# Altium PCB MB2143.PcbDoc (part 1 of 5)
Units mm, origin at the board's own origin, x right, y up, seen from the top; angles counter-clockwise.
Board outline 70 x 70 mm, 4 copper layers (Top Layer, Signal Layer 1, Signal Layer 2, Bottom Layer), stack 1.56 mm thick; 272 components, 188 nets, 1083 pads, 1158 vias.
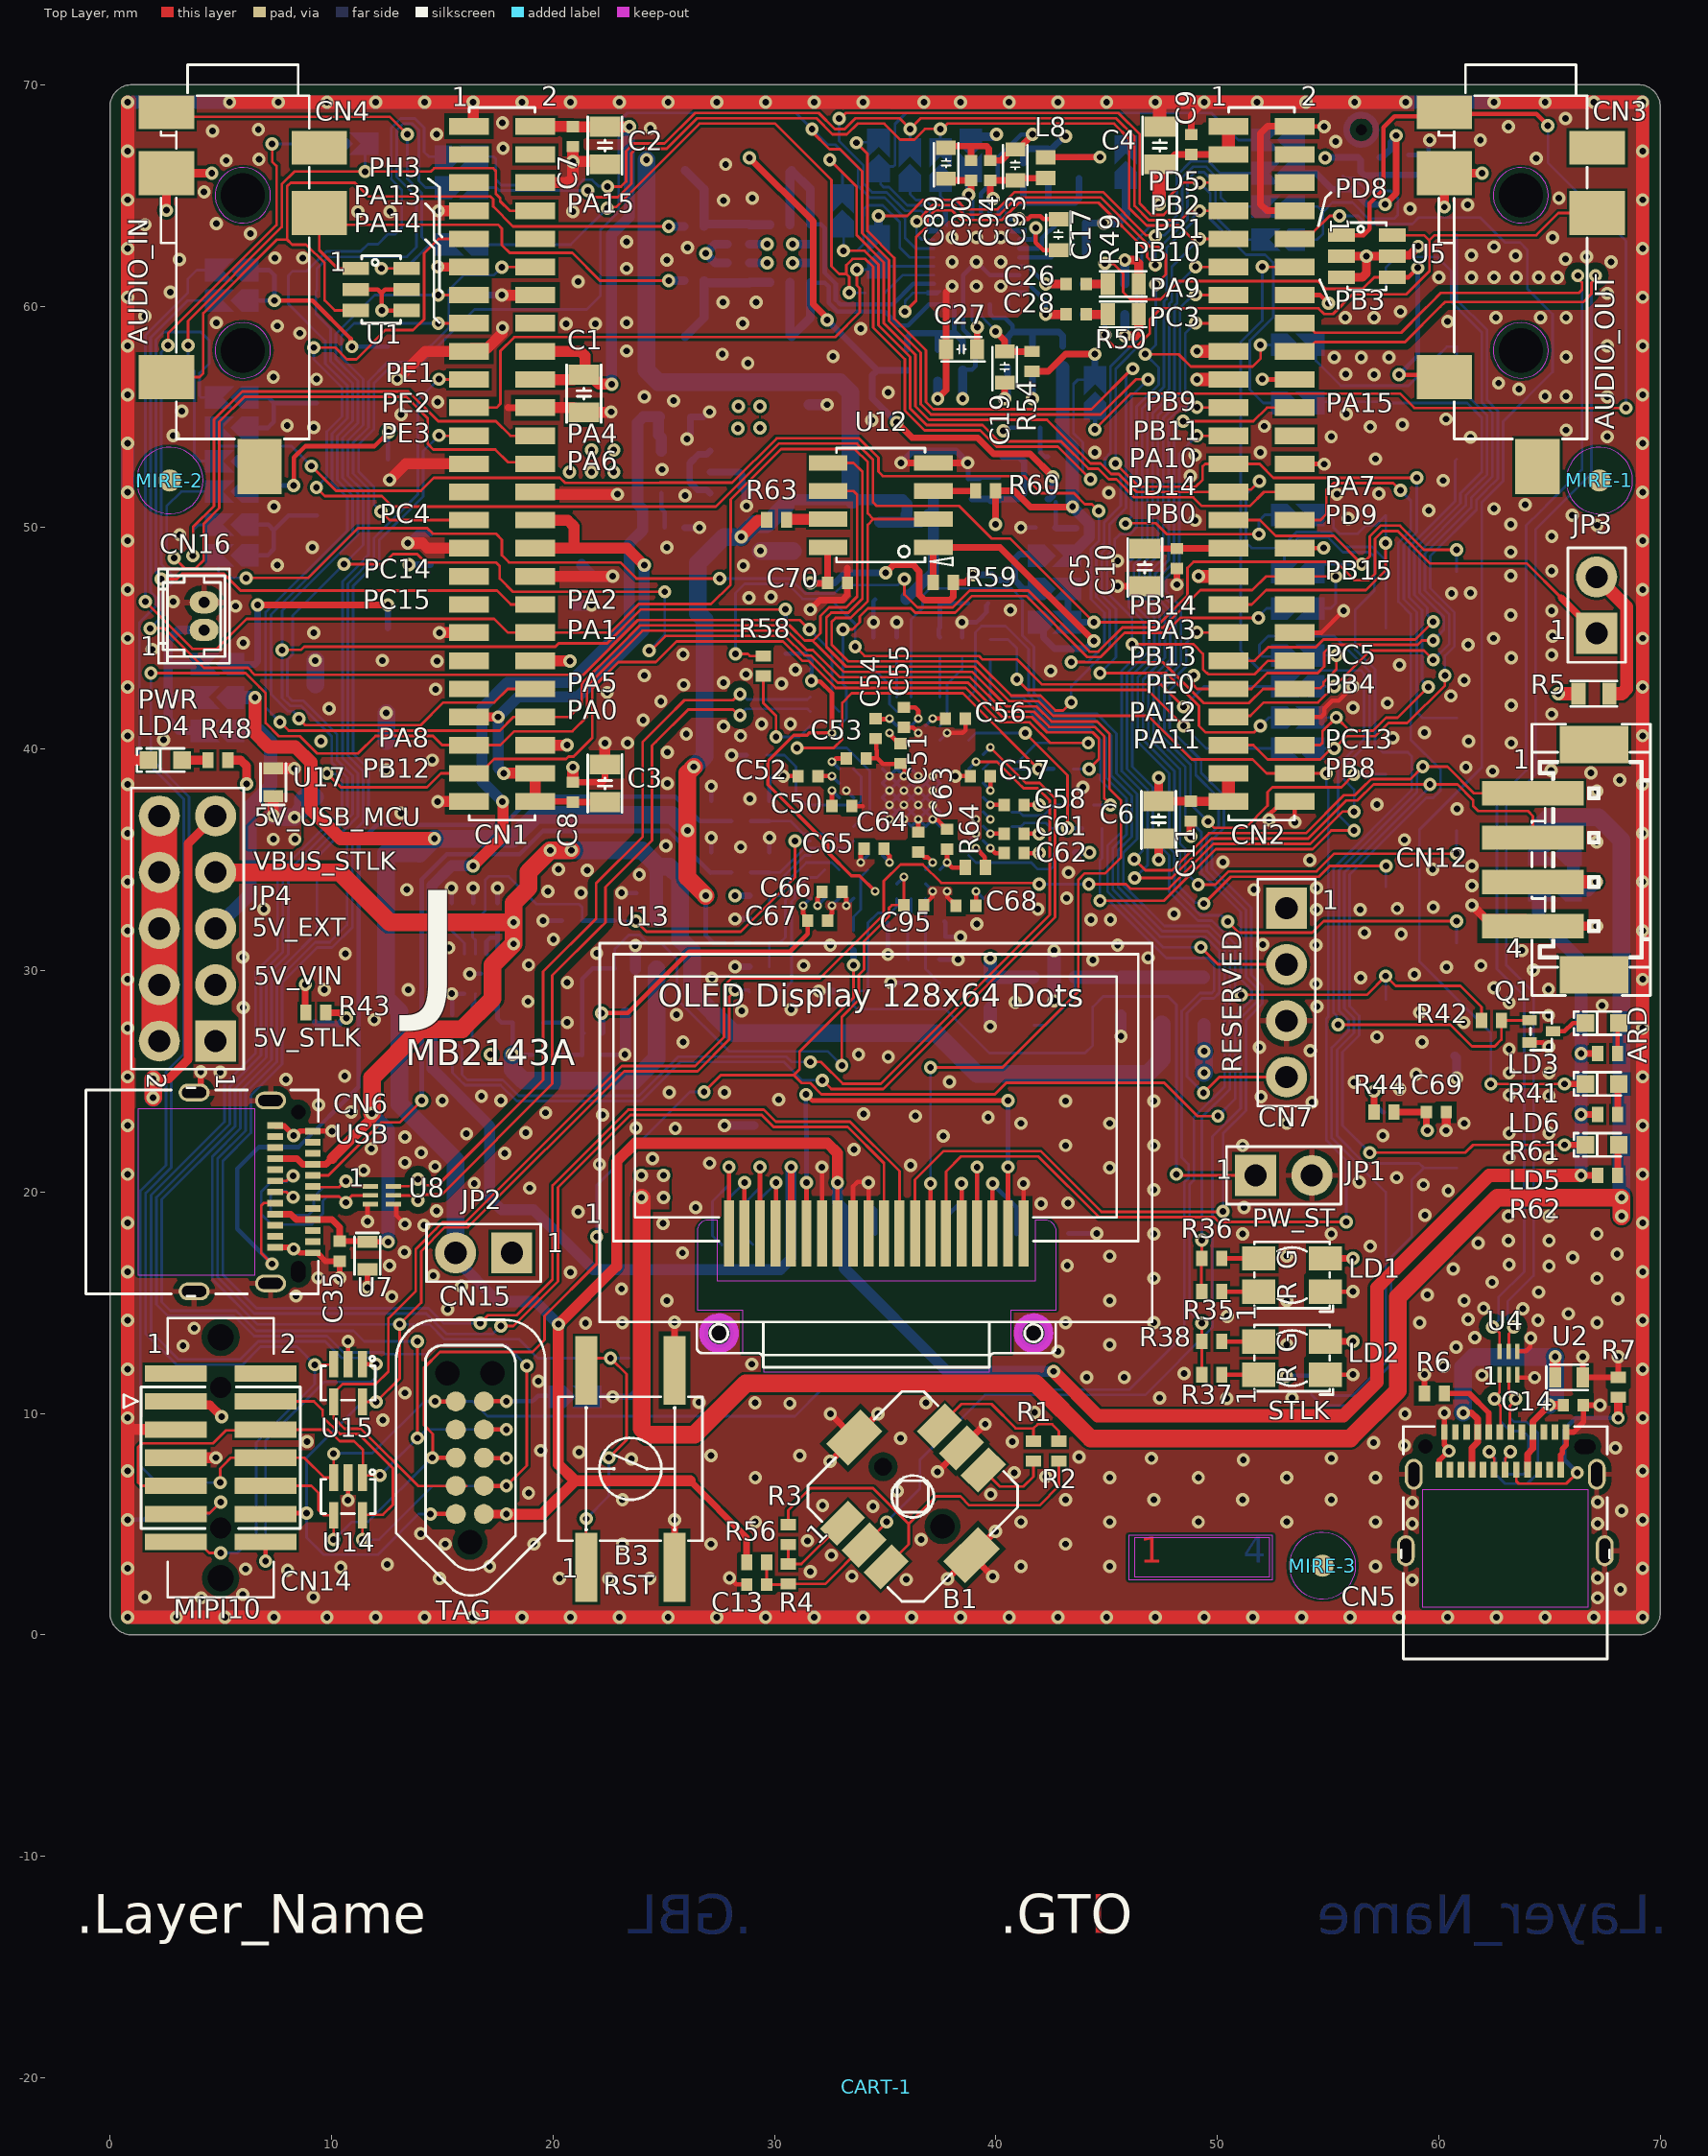
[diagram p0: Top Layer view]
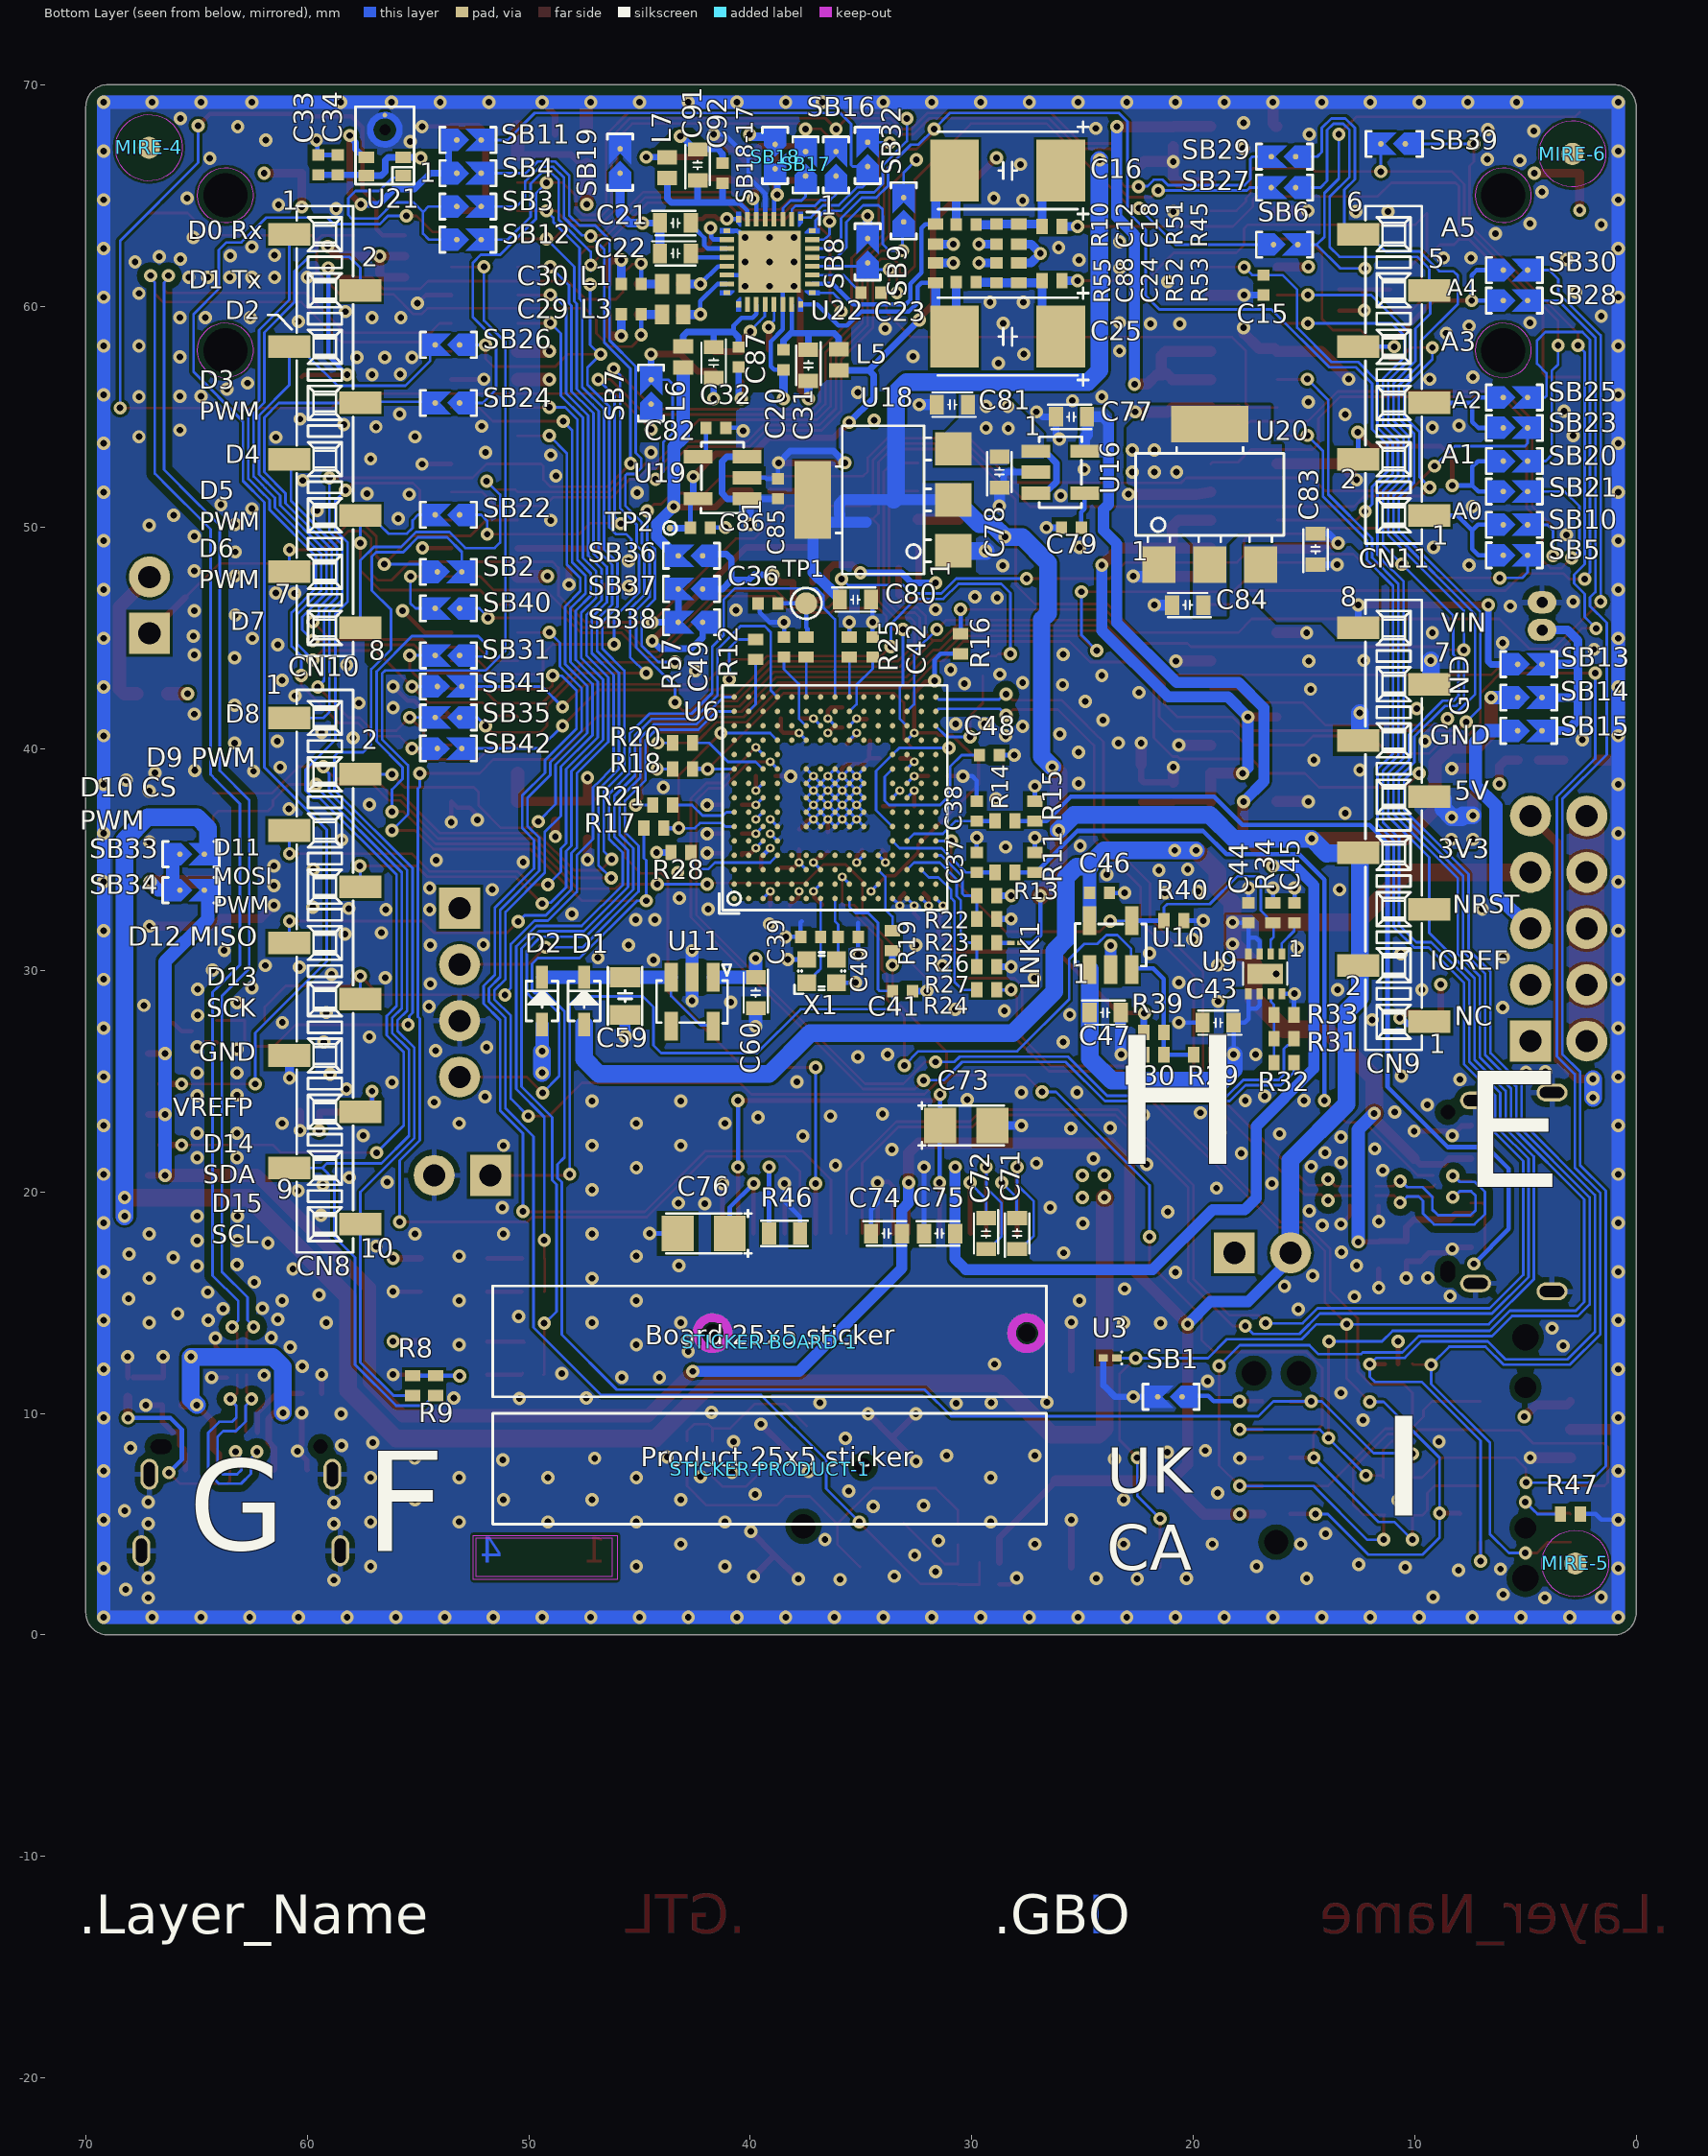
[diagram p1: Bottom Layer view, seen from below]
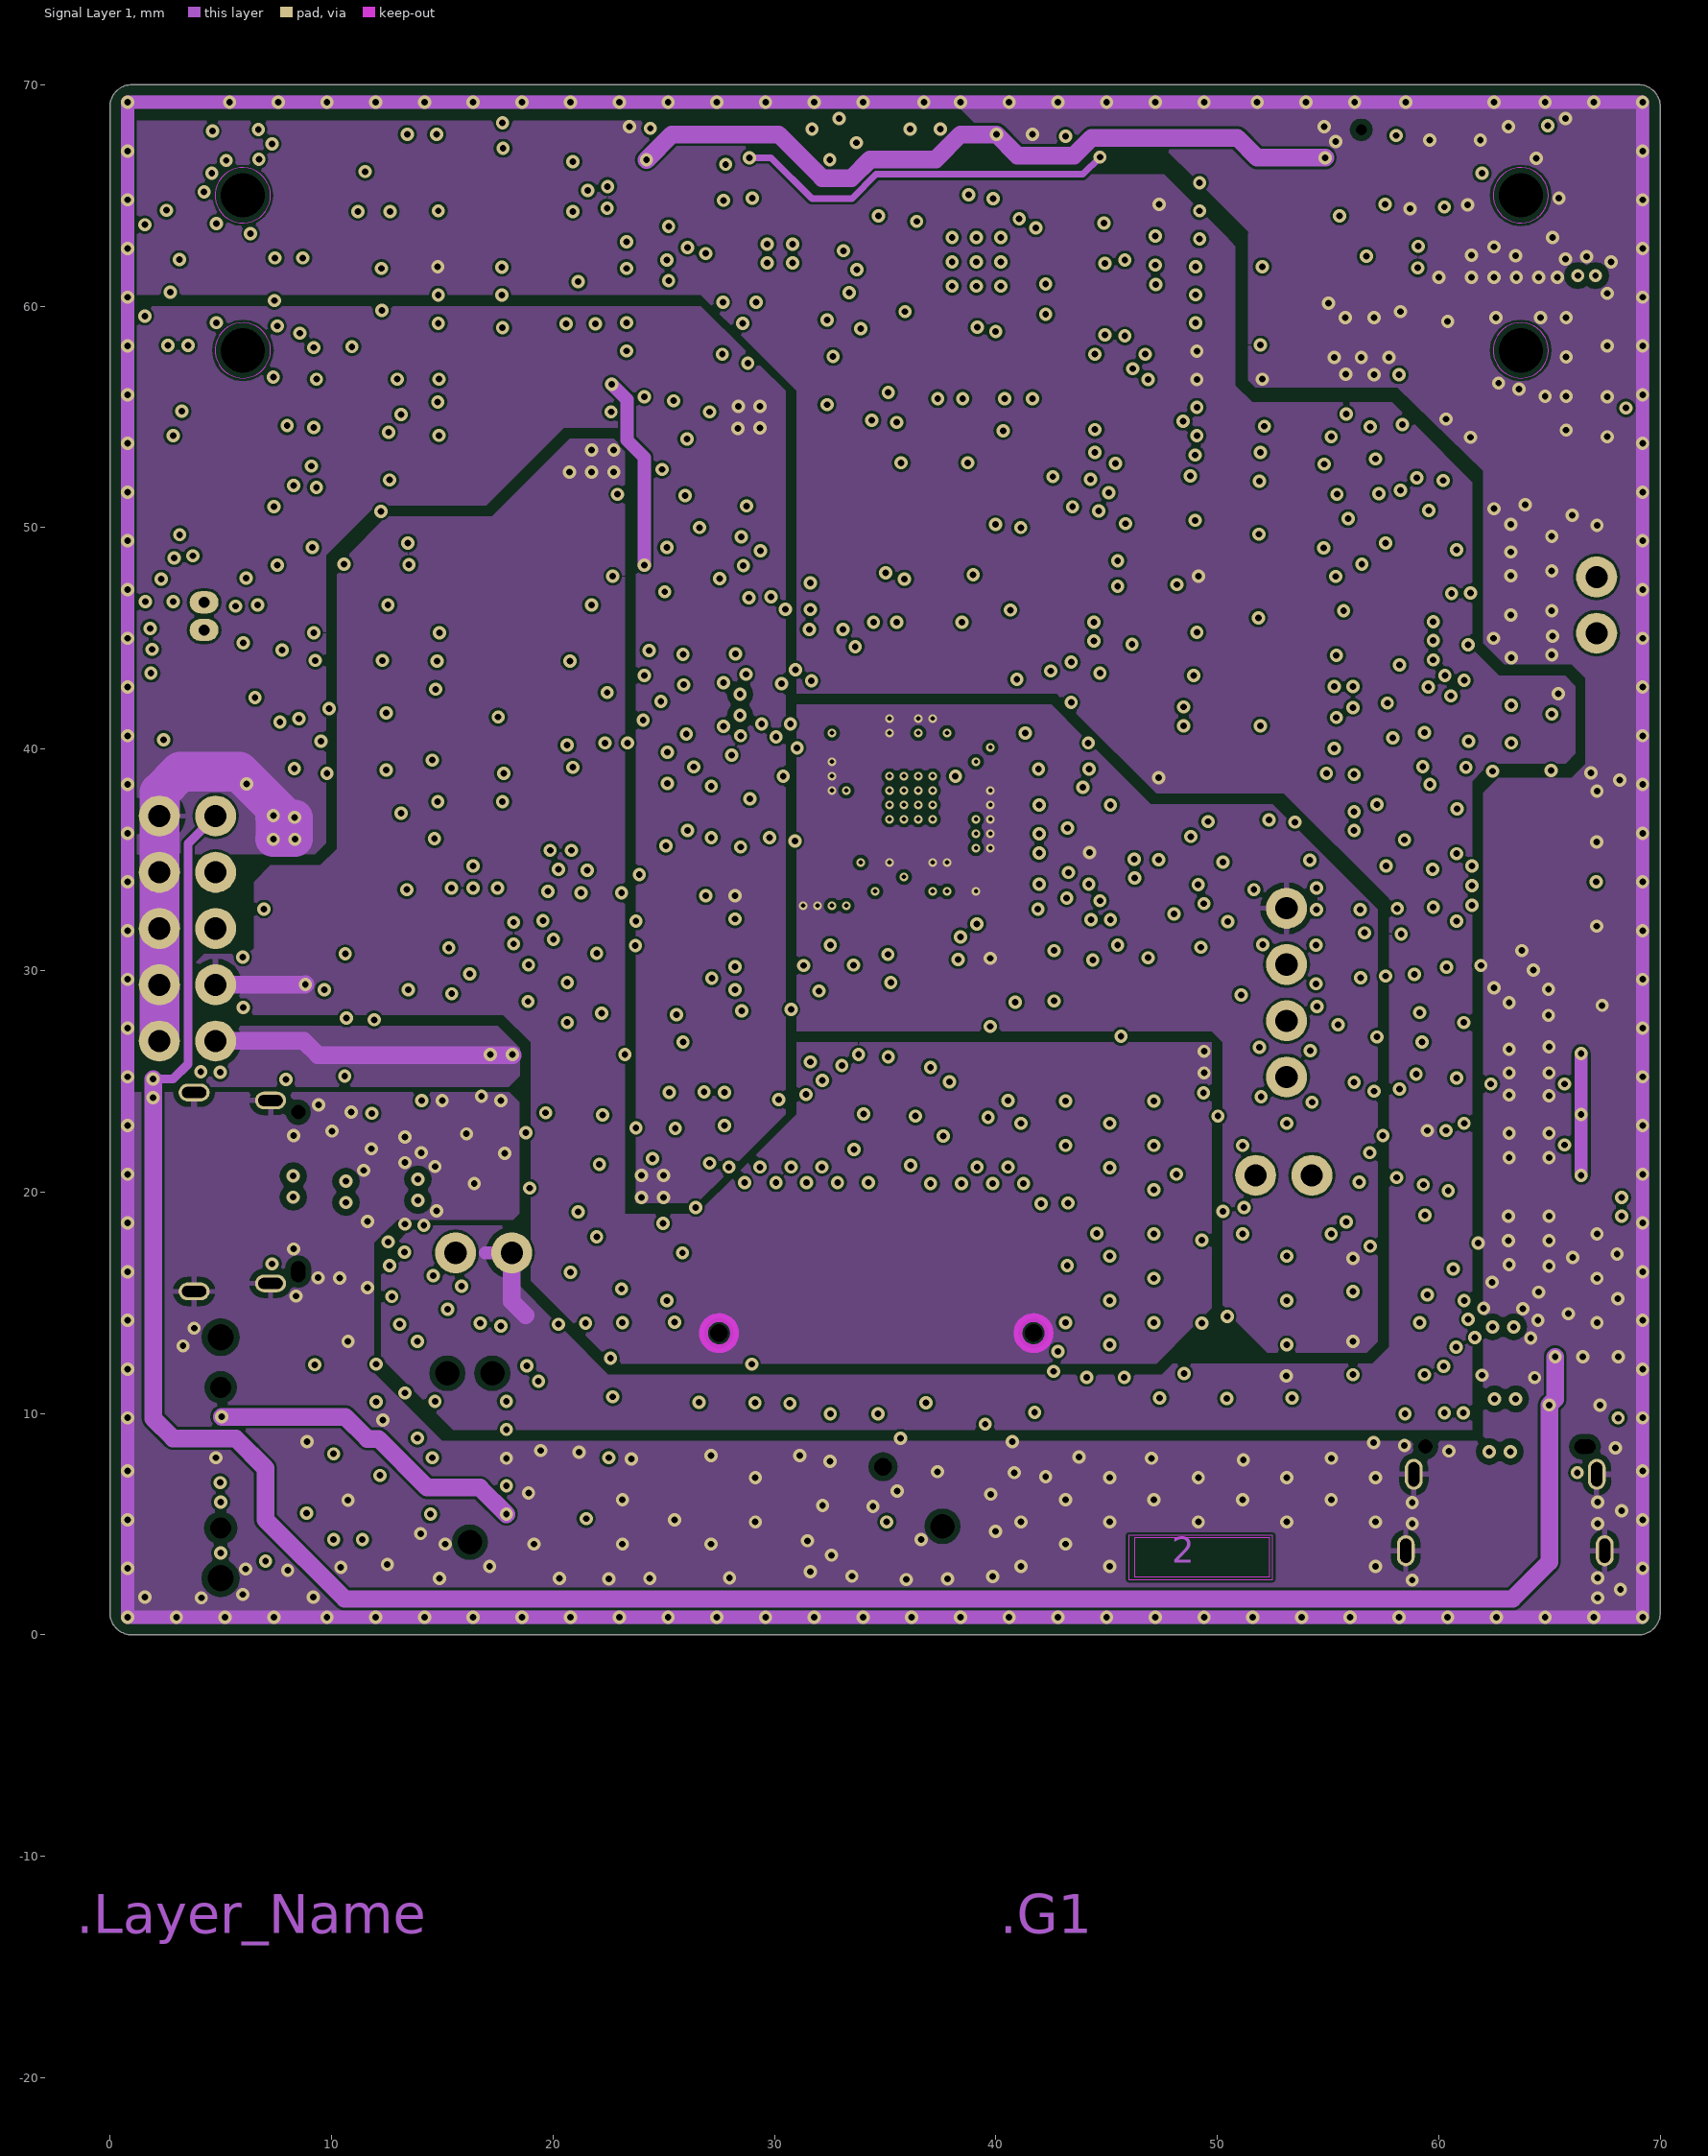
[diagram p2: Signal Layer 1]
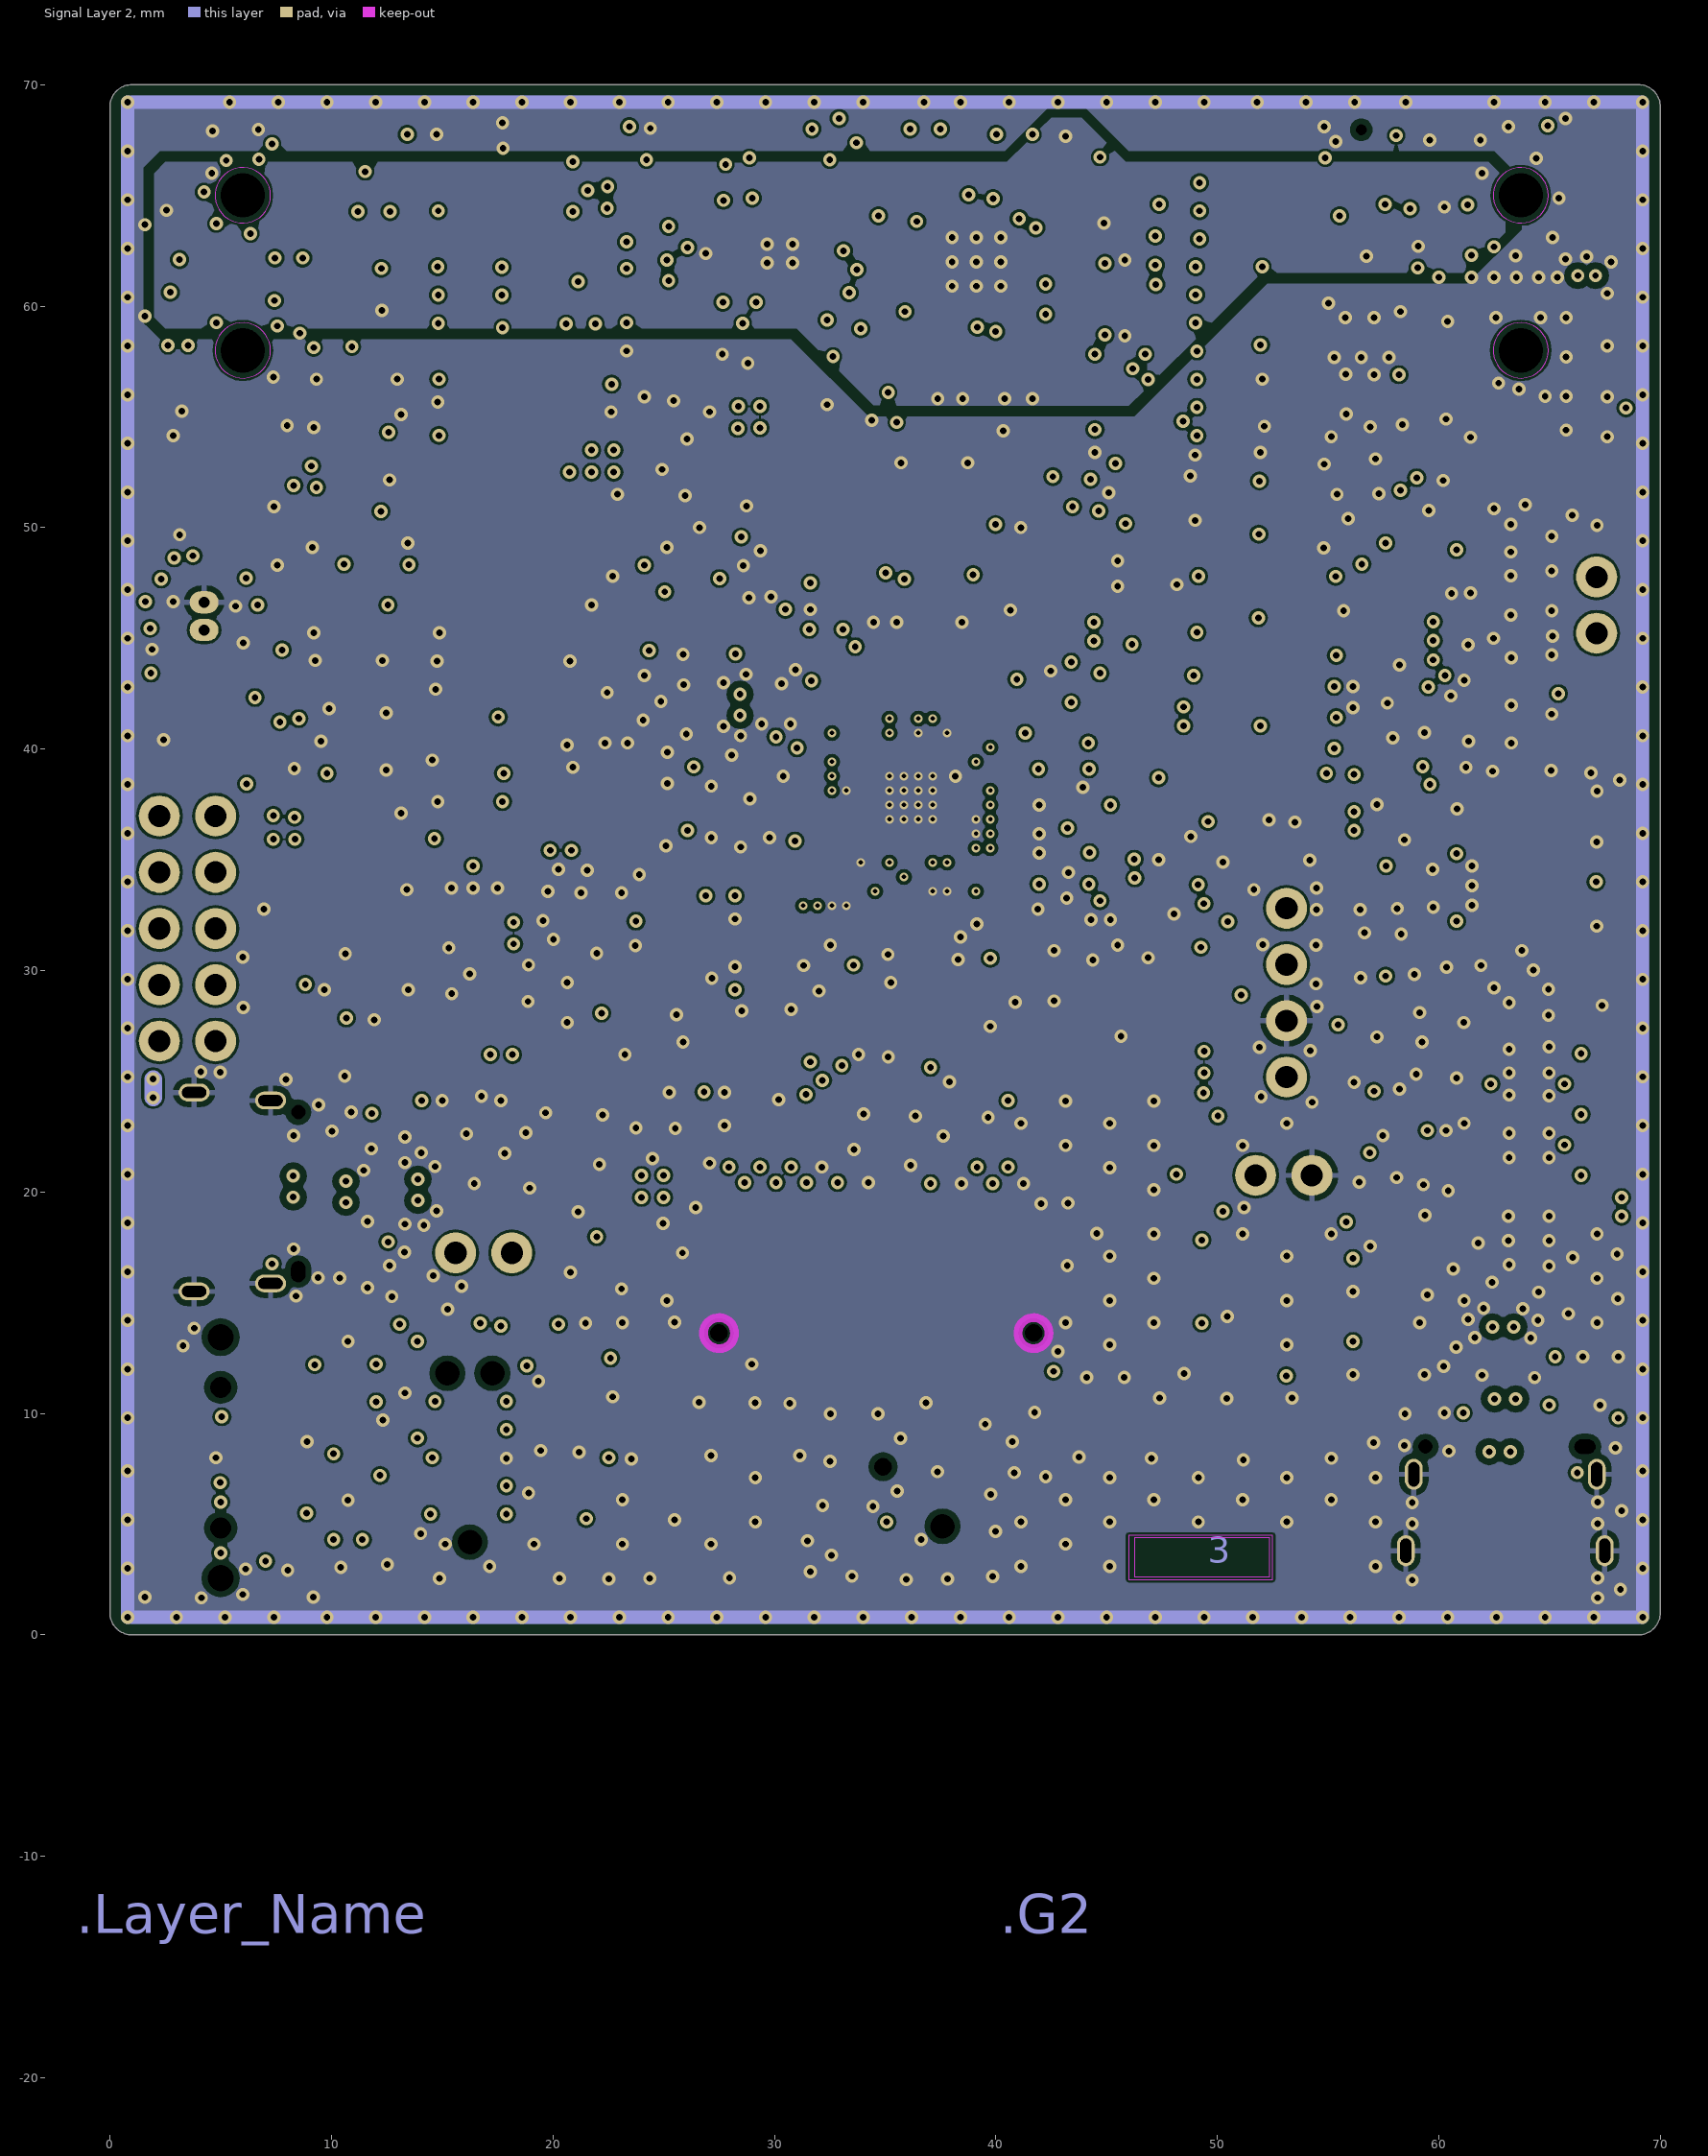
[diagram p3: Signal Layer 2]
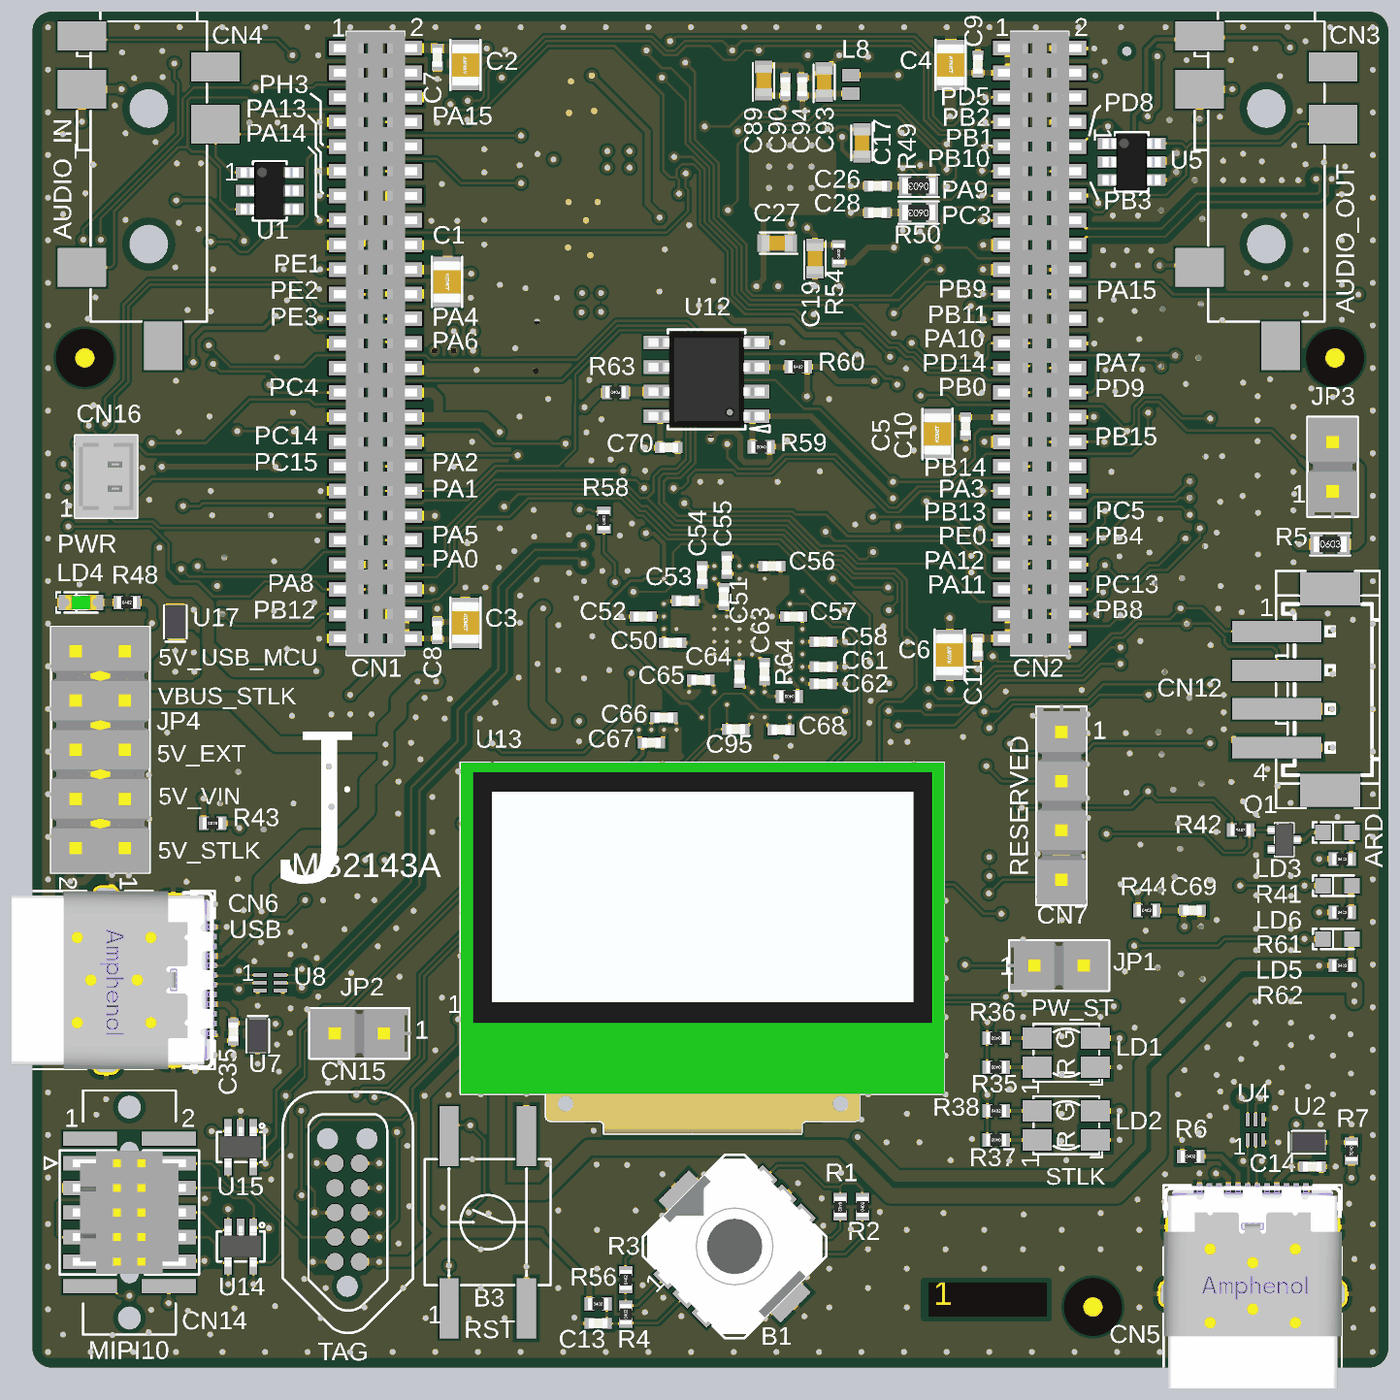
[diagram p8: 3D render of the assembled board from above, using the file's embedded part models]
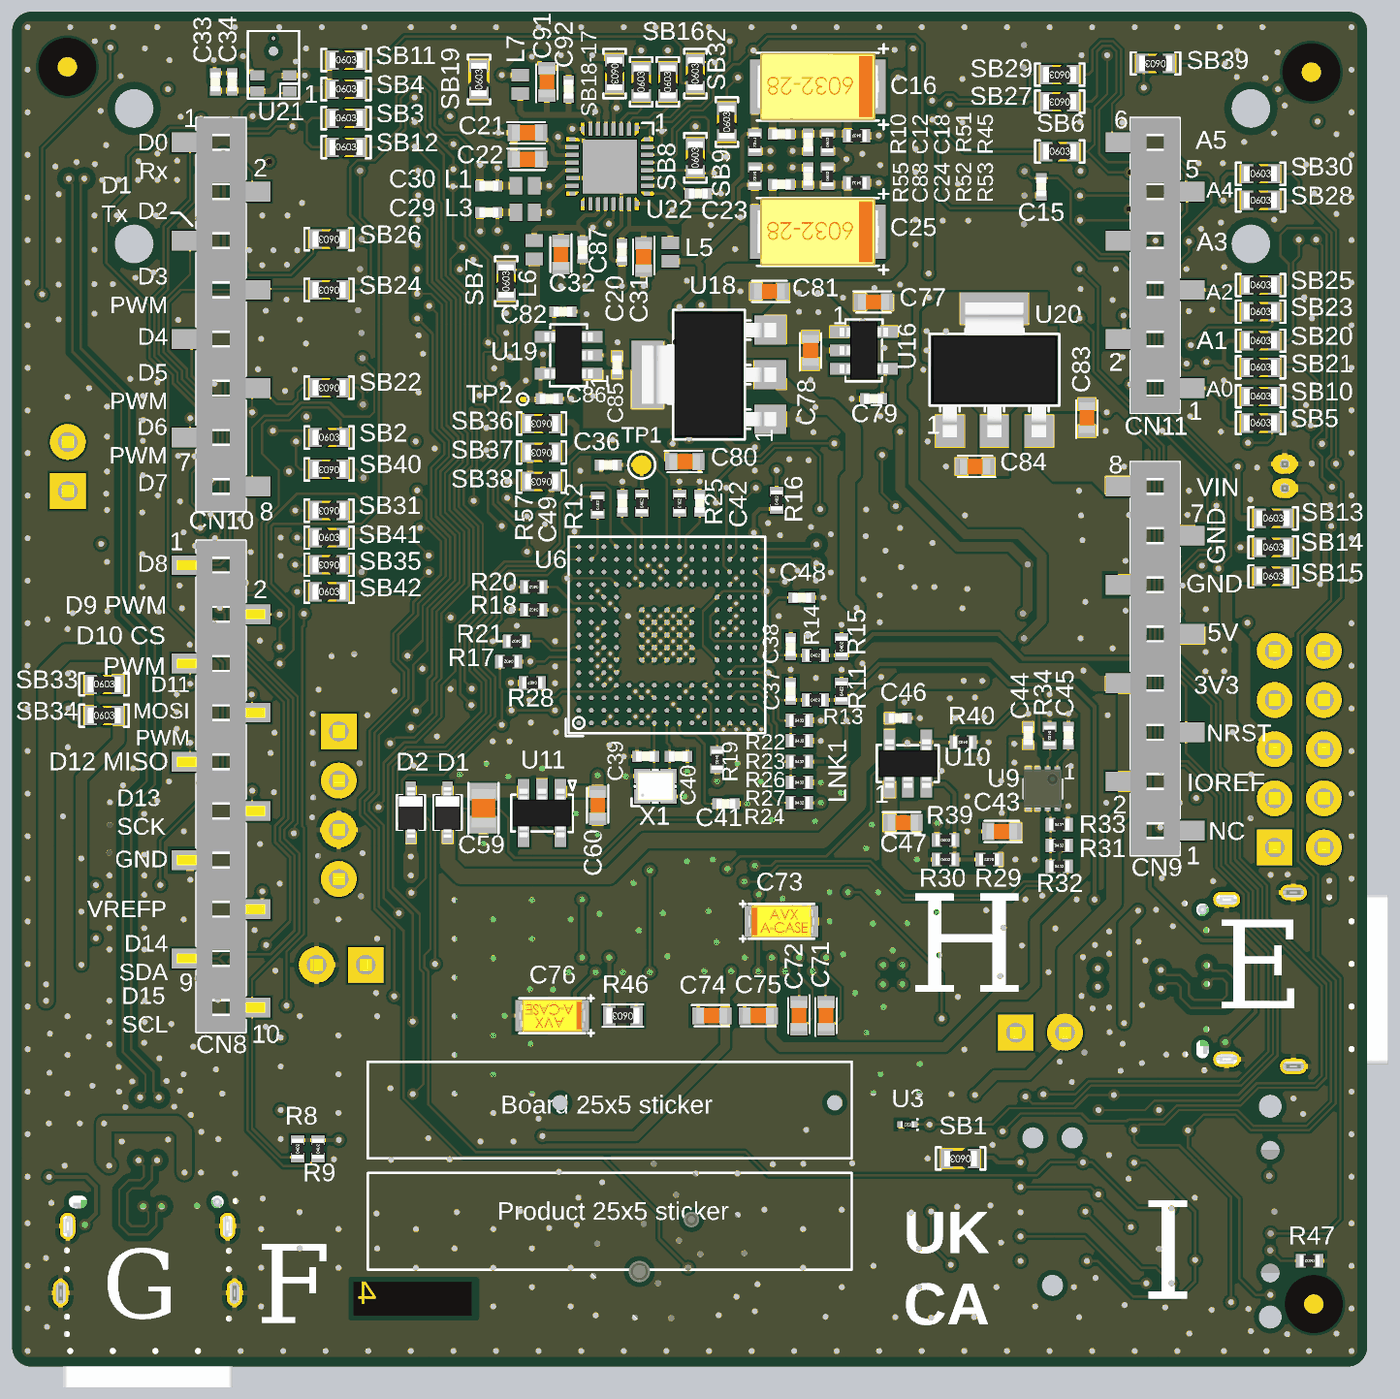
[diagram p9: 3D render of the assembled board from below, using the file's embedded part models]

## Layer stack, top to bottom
Top Solder: solder mask 0.02, Solder Resist, Dk 3.5
Top Layer: signal copper 0.054
Dielectric 1: prepreg 0.076, 1080HR RC68, Dk 4.2
Signal Layer 1: signal copper 0.035
Dielectric 2: core 1.23, FR4, Dk 4.5
Signal Layer 2: signal copper 0.035
Dielectric 3: prepreg 0.076, 1080HR RC68, Dk 4.2
Bottom Layer: signal copper 0.054
Bottom Solder: solder mask 0.02, Solder Resist, Dk 3.5

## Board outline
1,70 1.5,70 69,70 cw(c69,69) 70,69 70,1 cw(c69,1) 69,0 1,0 cw(c1,1) 0,1 0,69 cw(c1,69)

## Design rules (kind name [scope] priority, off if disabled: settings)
BoardOutlineClearance [All] p1: gap=0.5 ignorepadtopadclearanceinfootprint=FALSE
Clearance Clearance_USB_DIFFP-90R [InNetClass('NC__USB_DIFFP-90R')] p1: gap=0.3 ignorepadtopadclearanceinfootprint=TRUE except(0.15: SMDPad-Via; 0.2: Arc-SMDPad Arc-Via Track-SMDPad Track-Via Via-Via Via-Text Via-Hole; 0.25: Arc-THPad Arc-Hole Track-THPad Track-Hole)
Clearance Clearance_Default_Same-net [All] p2: gap=0.12 ignorepadtopadclearanceinfootprint=TRUE except(0: SMDPad-Via SMDPad-Hole; 0.1: THPad-Via; 0.24: Arc-Hole Track-Hole; 0.25: THPad-Hole Via-Via Via-Hole Fill-Hole Poly-Hole Region-Hole Text-Hole)
Clearance Clearance_Default [All] p3: gap=0.12 ignorepadtopadclearanceinfootprint=TRUE except(0.2: Arc-Hole Track-Hole SMDPad-Hole THPad-Hole Via-Hole Fill-Hole Poly-Hole Region-Hole Text-Hole; 0.25: Via-Via)
ComponentClearance [All] p1: gap=0 collisioncheckmode=3 verticalgap=0 showdistances=FALSE
DiffPairsRouting DiffPairsRouting_USB_DIFFP-90R [InDifferentialPairClass('DIFFC__USB_DIFFP-90R')] p1: maxlimit=0.3 minlimit=0.12 mostfreqgap=0.3 toplayer_mingap=0.3 toplayer_minwidth=0.12 toplayer_maxwidth=0.12 toplayer_prefwidth=0.12 bottomlayer_mingap=0.3 bottomlayer_minwidth=0.12 bottomlayer_maxwidth=0.12 bottomlayer_prefwidth=0.12 impedanceprofiledriven=TRUE impedanceprofileid={BBA45B2F-0BA6-4604-B683-008D44AAF67D} impedanceprofilevalue=90.000000 maxuncoupledlength=12.7
Height Height_5MM_BOTTOM [OnBottomLayer and WithinRoom('HMAX 5MM')] p1: minheight=0 maxheight=5 prefheight=5
Height [All] p2: minheight=0 maxheight=40 prefheight=40
HoleSize [All] p1: absolutevalues=TRUE maxlimit=10 minlimit=0.025 maxpercent=80.000 minpercent=20.000
HoleToHoleClearance [InDrillLayerPair('Top Layer - Bottom Layer') vs InDrillLayerPair('Top Layer - Bottom Layer')] p1: gap=0.3 allowstackedmicrovias=TRUE
MatchedLengths MatchedLengths_USB_DIFFP-90R [InDifferentialPairClass('DIFFC__USB_DIFFP-90R')] p1: tolerance=2 checknetsindiffpair=TRUE checkdiffpairvsdiffpair=FALSE checkxsignals=FALSE checkothers=FALSE
MaxMinImpedance "Schematic Impedance Constraint_3" [InNet('USB_C_P')] p1: minimum=85.00 maximum=95.00
MaxMinImpedance "Schematic Impedance Constraint_2" [InNet('USB_HS_N')] p2: minimum=85.00 maximum=95.00
MaxMinImpedance "Schematic Impedance Constraint_1" [InNet('USB_HS_P')] p3: minimum=85.00 maximum=95.00
MaxMinImpedance "Schematic Impedance Constraint" [InNet('USB_C_N')] p4: minimum=85.00 maximum=95.00
MaxMinImpedance "Schematic Impedance Constraint_11" [InNet('STLK_USB_CN_P')] p5: minimum=85.00 maximum=95.00
MaxMinImpedance "Schematic Impedance Constraint_10" [InNet('STLK_USB_CN_N')] p6: minimum=85.00 maximum=95.00
MaxMinImpedance "Schematic Impedance Constraint_9" [InNet('STLK_USB_P')] p7: minimum=85.00 maximum=95.00
MaxMinImpedance "Schematic Impedance Constraint_8" [InNet('STLK_USB_N')] p8: minimum=85.00 maximum=95.00
MinimumSolderMaskSliver [All] p1: minsoldermaskwidth=0.1
PolygonConnect PolygonConnect_Default [All] p1: thpad.connectstyle=Relief thpad.reliefconductorwidth=0.25 thpad.reliefentries=4 thpad.polygonreliefangle="90 Angle" thpad.airgapwidth=0.25 smdpad.connectstyle=NoConnect smdpad.reliefconductorwidth=0.2 smdpad.reliefentries=4 smdpad.polygonreliefangle="90 Angle" smdpad.airgapwidth=0.2 via.connectstyle=Direct via.reliefconductorwidth=0.2 via.reliefentries=4 via.polygonreliefangle="90 Angle" via.airgapwidth=0.2
RoomDefinition RoomDefinition_STLink [False vs False] p1: confinementstyle=ConfineIn formatcopy=TRUE lockcomponents=FALSE outline 40.5,43.075 40.5,32.425 31.25,32.425 31.25,43.075
RoutingLayers STLK__USB-90R [InDifferentialPairClass('DPC__STLK_USB-90R')] p1: top layer_v5=TRUE mid layer 1_v5=FALSE mid layer 4_v5=FALSE bottom layer_v5=TRUE
RoutingVias RoutingVias_PTH_L1-4_STLink [WithinRoom('RoomDefinition_STLink')and TouchesRoom('RoomDefinition_STLink')] p1: holewidth=0.2 width=0.45 viastyle="Through Hole" minholewidth=0.2 minwidth=0.45 maxholewidth=0.2 maxwidth=0.45 useviatemplates=TRUE viatemplateguid#1={76AE961C-B94A-4189-ABBD-1D46B8F7D8D9} viatemplateguid#2={A56F66F5-4D5B-4070-861C-FD4046CCDA41} viatemplatename#1=v40h20m0mx0 viatemplatename#2=v60h30m35mx35
RoutingVias RoutingVias_PTH_L1-4_Default_1 [All] p2: holewidth=0.2 width=0.45 viastyle="Through Hole" minholewidth=0.2 minwidth=0.45 maxholewidth=0.2 maxwidth=0.45 useviatemplates=TRUE viatemplateguid#1={A56F66F5-4D5B-4070-861C-FD4046CCDA41} viatemplatename#1=v60h30m35mx35
SilkToSilkClearance [All] p1: silktosilkclearance=0.2
SilkToSolderMaskClearance [IsPad] p1: minsilkscreentomaskgap=0.2 clearancetoexposedcopper=TRUE
SolderMaskExpansion [All] p1: expansion=0.102 istentingtop=FALSE
UnRoutedNet [All] p1: checkbadconnections=TRUE
ViasUnderSMD [All] p1: allowed=TRUE
Width Width_ALIMS_300um [InNetClass('NC__ALIMS__300um')] p1: maxlimit=0.3 minlimit=0.15 preferedwidth=0.3
Width Width_ALIMS_500um [InNetClass('NC__ALIMS__500um')] p2: maxlimit=0.5 minlimit=0.15 preferedwidth=0.5
Width Width_ALIMS_800um [InNetClass('NC__ALIMS__800um')] p3: maxlimit=10 minlimit=0.15 preferedwidth=0.8
Width Width_GND [InNetClass('NC__GND')] p4: maxlimit=10 minlimit=0.15 preferedwidth=0.3
Width Width_Default [All] p5: maxlimit=10 minlimit=0.12 preferedwidth=0.12
20 further rules are at their usual default settings.

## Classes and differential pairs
net class NC__GND: AVDD GND
net class NC__ALIMS__300um: 1V8 CPVDD DBVDD DCVDD MICVDD VIN
net class NC__ALIMS__800um: 3V3 3V3_STLK 3V6 5V 5V_EXT 5V_STLK 5V_USB_MCU 5V_VIN VBUS_STLK
differential pair class DIFFC__USB_DIFFP-90R: STLK_USB STLK_USB_CN USB_C USB_HS
net class NC__USB_DIFFP-90R: STLK_USB_CN_N STLK_USB_CN_P STLK_USB_N STLK_USB_P USB_C_N USB_C_P USB_HS_N USB_HS_P
component class U_STLink_V3EC: C35 C36 C37 C38 C39 C40 C41 C42 C43 C44 C45 C46 C47 C48 C49 C50 C51 C52 C53 C54 C55 C56 C57 C58 C59 C60 C61 C62 C63 C64 C65 C66 C67 C68 C95 CN6 CN7 D1 D2 JP1 LD1 LD2 LNK1 R11 R12 R13 R14 R15 R16 R17 R18 R19 R20 R21 R22 R23 R24 R25 R26 R27 R28 R29 R30 R31 R32 R33 R34 R35 R36 R37 R38 R39 R40 R57 R58 R64 TP1 U6 U7 U8 U9 U10 U11 X1
component class U_OLED: C71 C72 C73 C74 C75 C76 R46 U13
component class U_MCU: C1 C2 C3 C4 C5 C6 C7 C8 C9 C10 C11 C70 CN1 CN2 HW5 HW6 JP3 LD5 LD6 R5 R8 R9 R59 R60 R61 R62 R63 SB31 SB35 SB36 SB37 SB38 SB39 SB40 SB41 SB42 U12
component class U_USB_Joystick_Reset: B1 B3 C13 C14 C15 CN5 R1 R2 R3 R4 R6 R7 R56 U2 U3 U4
component class U_External_Debug_Interface: CN14 CN15 R47 SB1 U14 U15
component class U_Board_Power: C77 C78 C79 C80 C81 C82 C83 C84 C85 C86 CN16 HW3 HW4 JP2 JP4 LD4 R48 SB13 SB14 SB15 TP2 U16 U17 U18 U19 U20
component class U_Audio_Codec: C12 C16 C17 C18 C19 C20 C21 C22 C23 C24 C25 C26 C27 C28 C29 C30 C31 C32 C33 C34 C87 C88 C89 C90 C91 C92 C93 C94 CN3 CN4 L1 L3 L5 L6 L7 L8 R10 R45 R49 R50 R51 R52 R53 R54 R55 SB3 SB4 SB6 SB7 SB11 SB12 SB16 SB17 SB18 SB19 SB32 U1 U5 U21 U22
component class U_Arduino: C69 CN8 CN9 CN10 CN11 CN12 LD3 Q1 R41 R42 R43 R44 SB2 SB5 SB8 SB9 SB10 SB20 SB21 SB22 SB23 SB24 SB25 SB26 SB27 SB28 SB29 SB30 SB33 SB34
differential pair USB_HS: +USB_HS_P -USB_HS_N
differential pair USB_C: +USB_C_P -USB_C_N
differential pair STLK_USB: +STLK_USB_P -STLK_USB_N
differential pair STLK_USB_CN: +STLK_USB_CN_P -STLK_USB_CN_N

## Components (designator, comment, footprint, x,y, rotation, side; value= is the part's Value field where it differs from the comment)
B1 "Joystick MT-008A_M" SWI_XIEJIA_MT-008A_6P 36.25,6.25 r45 top value=MT-008A
B3 "SW_BLACK_KSC321GLFS" SWI_C&K_KSC321GLFS_BLACK 23.5,7.5 r90 top value=KSC321GLFS
C1 "Capacitor" C0805_H0P85 21.4,56.05 r270 top value=1uF
C2 "Capacitor" C0805_H0P85 22.35,67.25 r90 top value=1uF
C3 "Capacitor" C0805_H0P85 22.35,38.45 r270 top value=1uF
C4 "Capacitor" C0805_H0P85 47.4,67.25 r270 top value=1uF
C5 "Capacitor" C0805_H0P85 46.725,48.2 r90 top value=1uF
C6 "Capacitor" C0805_H0P85 47.35,36.8 r90 top value=1uF
C7 "Capacitor" C0402 20.9,67.65 r90 top value=100nF
C8 "Capacitor" C0402 20.9,38.05 r90 top value=100nF
C9 "Capacitor" C0402 48.815,67.295 r270 top value=100nF
C10 "Capacitor" C0402 48.175,48.6 r90 top value=100nF
C11 "Capacitor" C0402 48.8,37.2 r90 top value=100nF
C12 "Capacitor" C0402 30.25,63.675 r0 bottom value=1uF
C13 "Capacitor" C0402 29.2,2.275 r0 top value=10nF
C14 "Capacitor" C0402 66.075,10.375 r180 top value=100pF
C15 "Capacitor" C0402 16.825,60.95 r90 bottom value=100nF
C16 "Cap_POL_TANA" C6032-28_VISHAY_293D-CASE-C 28.375,66.125 r0 bottom value=10uF
C17 "Capacitor" C0603 42.825,63.225 r90 top value=2.2uF
C18 "Capacitor" C0402 28.875,63.25 r90 bottom value=220pF
C19 "Capacitor" C0603 40.4,57.25 r270 top value=4.7uF
C20 "Capacitor" C0402 38.5,57.575 r90 bottom value=100nF
C21 "Capacitor" C0603 43.375,63.75 r0 bottom value=2.2uF
C22 "Capacitor" C0603 43.375,62.375 r0 bottom value=2.2uF
C23 "Capacitor" C0402 34.55,60.6 r180 bottom value=1uF
C24 "Capacitor" C0402 28.875,61.5 r90 bottom value=220pF
C25 "Cap_POL_TANA" C6032-28_VISHAY_293D-CASE-C 28.375,58.625 r0 bottom value=10uF
C26 "Capacitor" C0402 43.625,61 r0 top value=100nF
C27 "Capacitor" C0603 38.45,58.05 r0 top value=4.7uF
C28 "Capacitor" C0402 43.625,59.625 r0 top value=100nF
C29 "Capacitor" C0402 45.375,59.625 r180 bottom value=470pF
C30 "Capacitor" C0402 45.375,61 r180 bottom value=470pF
C31 "Capacitor" C0603 37.375,57.325 r90 bottom value=4.7uF
C32 "Capacitor" C0603 41.65,57.45 r90 bottom value=4.7uF
C33 "Capacitor" C0402 59.5,66.375 r270 bottom value=100nF
C34 "Capacitor" C0402 58.625,66.375 r90 bottom value=1uF
C35 "Capacitor" C0402 10.375,17.325 r270 top value=100pF
C36 "Capacitor" C0402 39.2,46.575 r180 bottom value=20pF
C37 "Capacitor" C0402 29.775,34.88 r90 bottom value=10nF
C38 "Capacitor" C0402 29.775,37.2 r90 bottom value=10nF
C39 "Capacitor" C0402 37.275,31.52 r180 bottom value=5.6pF
C40 "Capacitor" C0402 35.575,31.52 r180 bottom value=5.6pF
C41 "Capacitor" C0402 33.125,29.075 r0 bottom value=100nF
C42 "Capacitor" C0402 34.475,44.6 r270 bottom value=2.2uF
C43 "Capacitor" C0603 18.875,27.645 r180 bottom value=10uF
C44 "Capacitor" C0402 17.5,32.6 r270 bottom value=100nF
C45 "Capacitor" C0402 15.425,32.6 r270 bottom value=10nF
C46 "Capacitor" C0402 24.225,33.5 r0 bottom value=100nF
C47 "Capacitor" C0603 23.975,28.1 r0 bottom value=10uF
C48 "Capacitor" C0402 29.2,39.725 r0 bottom value=2.2uF
C49 "Capacitor" C0402 38.475,44.6 r270 bottom value=2.2uF
C50 "Capacitor" C0402 33.05,37.425 r0 top value=100nF
C51 "Capacitor" C0402 35.7,39.8 r270 top value=100nF
C52 "Capacitor" C0402 31.525,38.775 r180 top value=100nF
C53 "Capacitor" C0402 33.7,39.58 r0 top value=100nF
C54 "Capacitor" C0402 34.575,40.925 r270 top value=100nF
C55 "Capacitor" C0402 35.85,41.425 r270 top value=100nF
C56 "Capacitor" C0402 38.175,41.375 r0 top value=100nF
C57 "Capacitor" C0402 39.3,38.775 r180 top value=100nF
C58 "Capacitor" C0402 40.825,37.475 r0 top value=100nF
C59 "Capacitor" C0805 45.65,28.845 r90 bottom value=2.2uF
C60 "Capacitor" C0603 39.75,28.995 r90 bottom value=10uF
C61 "Capacitor" C0402 40.825,36.175 r0 top value=100nF
C62 "Capacitor" C0402 40.825,35.3 r0 top value=100nF
C63 "Capacitor" C0402 37.8,35.925 r90 top value=100nF
C64 "Capacitor" C0402 36.5,35.8 r90 top value=100nF
C65 "Capacitor" C0402 34.5,35.5 r180 top value=100nF
C66 "Capacitor" C0402 32.6,33.55 r0 top value=100nF
C67 "Capacitor" C0402 31.95,32.25 r0 top value=100nF
C68 "Capacitor" C0402 38.65,32.925 r180 top value=100nF
C69 "" C0402 59.89,23.602 r0 top value=100nF
C70 "Capacitor" C0402 32.85,47.5 r180 top value=100nF
C71 "" C0603 27.95,18.125 r270 bottom value=1uF
C72 "" C0603 29.35,18.125 r90 bottom value=1uF
C73 "​Footprint CPOL_TAJ-A_1206_H180" CPOL_TAJ-A_1206_H180 30.25,23 r180 bottom value=4.7uF
C74 "" C0603 33.85,18.125 r0 bottom value=1uF
C75 "" C0603 31.45,18.125 r0 bottom value=1uF
C76 "​Footprint CPOL_TAJ-A_1206_H180" CPOL_TAJ-A_1206_H180 42.1,18.125 r0 bottom value=4.7uF
C77 "Capacitor" C0603 25.5,55 r0 bottom value=2.2uF
C78 "Capacitor" C0603 28.75,52.5 r270 bottom value=1uF
C79 "Capacitor" C0402 25.5,50 r0 bottom value=10nF
C80 "Capacitor" C0603 35.25,46.75 r0 bottom value=10uF
C81 "Capacitor" C0603 30.875,55.55 r180 bottom value=10uF
C82 "Capacitor" C0402 41.544,54.506 r0 bottom value=10nF
C83 "Capacitor" C0603 14.475,49.025 r270 bottom value=10uF
C84 "Capacitor" C0603 20.25,46.5 r180 bottom value=10uF
C85 "Capacitor" C0402 38.75,51.75 r270 bottom value=1uF
C86 "Capacitor" C0402 42.25,50 r0 bottom value=1uF
C87 "Capacitor" C0402 40.525,57.7 r90 bottom value=100nF
C88 "Capacitor" C0402 30.25,61.075 r0 bottom value=1uF
C89 "Capacitor" C0603 37.75,66.45 r270 top value=4.7uF
C90 "Capacitor" C0402 38.875,66.125 r270 top value=100nF
C91 "Capacitor" C0603 42.375,66.375 r270 bottom value=4.7uF
C92 "Capacitor" C0402 41.25,66 r270 bottom value=100nF
C93 "Capacitor" C0603 40.875,66.375 r270 top value=4.7uF
C94 "Capacitor" C0402 39.75,66.125 r270 top value=100nF
C95 "Capacitor" C0402 36.3,32.95 r0 top value=10nF
CART-1 "Comment" Sheetbox_4L2S -10.5,-25.75 r0 top
CN1 "CLP-125-02-F-D" CON_SAMTEC_CLP-125-02-F-D 17.71,52.875 r0 top value="Socket 25x2"
CN2 "CLP-125-02-F-D" CON_SAMTEC_CLP-125-02-F-D 52,52.875 r0 top value="Socket 25x2"
CN3 "Jack_PJ3028B-3_4P" CON_PHONE-JACK-3P5_HY_PJ3028B 63.7,70 r270 top value=PJ3028B-3_4P
CN4 "Jack_PJ3028B-3_4P" CON_PHONE-JACK-3P5_HY_PJ3028B 6,70 r270 top value=PJ3028B-3_4P
CN5 "USB_TYPE_C_Receptacle" CON_USB-TYPEC_AMPHENOL_12401826E412A 63,8.5 r0 top value=USB_C_12401826E412A
CN6 "USB_TYPE_C_Receptacle" CON_USB-TYPEC_AMPHENOL_12401826E412A 8.5,20 r270 top value=USB_C_12401826E412A
CN7 "Header 4x1" CON_SAMTEC_TSW-104-07-G-S 53.125,29 r270 top
CN8 "Socket 10x1" CON_SAMTEC_SSM-110-L-SV 59.206,29.973 r270 bottom value=SSM-110-L-SV
CN9 "Socket 8x1" CON_SAMTEC_SSM-108-L-SV 10.947,36.577 r90 bottom value=SSM-108-L-SV
CN10 "Socket 8x1" CON_SAMTEC_SSM-108-L-SV 59.206,54.357 r270 bottom value=SSM-108-L-SV
CN11 "Socket 6x1" CON_SAMTEC_SSM-106-L-SV 10.947,56.897 r90 bottom value=SSM-106-L-SV
CN12 "Header 4x1" CON_988-JIUBABA_A2006LF-04A 67,35 r90 top
CN14 "Header 7x2" CON_STDC14_Receiver_MEDIUM_WITH_MIPI10_3D 5,8 r270 top value="MIPI10 on STDC14 footprint"
CN15 "Tag-10-C" CON_TAG-C_TC2050-IDC-NL 16.25,8 r90 top value="Header 5x2"
CN16 "Header 2x1" CON_MOLEX_53047-0210 4.25,46 r90 top
D1 "SCHOTTKY_1A_2K" DIO_SOD323_1A_2K 47.5,28.625 r90 bottom value=BAT20JFILM
D2 "SCHOTTKY_1A_2K" DIO_SOD323_1A_2K 49.4,28.625 r90 bottom value=BAT20JFILM
JP1 "Jumper_Header 2x1" CON_SAMTEC_TSW-102-07-G-S 53,20.75 r0 top value="Header 2x1"
JP2 "Jumper_Header 2x1" CON_SAMTEC_TSW-102-07-G-S 16.875,17.25 r180 top value="Shunt for curent measurement."
JP3 "Jumper_Header 2x1" CON_SAMTEC_TSW-102-07-G-S 67.125,46.5 r90 top
JP4 "Jumper_Header 5x2 Fitted 1-2" CON_SAMTEC_TSW-105-07-X-D 3.5,31.895 r90 top value="Header 5x2"
L1 "Inductor" IND_0402_MURATA_BLM15H_H0P5 43.5,61 r0 bottom value="10R @100MHz"
L3 "Inductor" IND_0402_MURATA_BLM15H_H0P5 43.5,59.625 r0 bottom value="10R @100MHz"
L5 "Inductor" IND_0402_MURATA_BLM15H_H0P5 36,57.575 r90 bottom value="10R @100MHz"
L6 "Inductor" IND_0402_MURATA_BLM15H_H0P5 43.025,57.7 r90 bottom value="10R @100MHz"
L7 "Inductor" IND_0402_MURATA_BLM15H_H0P5 43.75,66.25 r270 bottom value="10R @100MHz"
L8 "Inductor" IND_0402_MURATA_BLM15H_H0P5 42.25,66.25 r270 top value="10R @100MHz"
LD1 "LED_BICOLOR" LED_BI-GR_WE-150141SV73110 53.375,16.25 r90 top value="Green / Red"
LD2 "LED_BICOLOR" LED_BI-GR_WE-150141SV73110 53.375,12.5 r90 top value="Green / Red"
LD3 "LED_blue" LED_0603_VISHAY_VLMB1300-GS08_BLUE_1A2K_H0P8 67.375,27.625 r180 top value=BLUE
LD4 "LED_green" LED_0603_OSRAM_LG-Q396-PS-35_GREEN_1A2K_H0P4 2.5,39.5 r180 top value=Green
LD5 "LED_red" LED_0603_VISHAY_VLMS1300-GS08_RED_1A2K_H0P8 67.375,22.125 r180 top value=RED
LD6 "LED_green" LED_0603_VISHAY_VLMTG1300-GS08_GREEN_1A2K_H0P8 67.375,24.875 r180 top value="TRUE GREEN"
LNK1 "link_200" LINK200 28.005,31.25 r90 bottom
MIRE-1 "Comment" MIRE_PLACE_SMD_1MM 67.25,52.125 r270 top
MIRE-2 "Comment" MIRE_PLACE_SMD_1MM 2.7,52.125 r270 top
MIRE-3 "Comment" MIRE_PLACE_SMD_1MM 54.75,3.125 r270 top
MIRE-4 "Comment" MIRE_PLACE_SMD_1MM 67.15,67.15 r90 bottom
MIRE-5 "Comment" MIRE_PLACE_SMD_1MM 2.75,3.225 r90 bottom
MIRE-6 "Comment" MIRE_PLACE_SMD_1MM 2.875,66.875 r90 bottom
Q1 "DTC043ZEBTL" NPN_SOT416-FL_EMT3F_1616_SC89 64.625,27.25 r270 top
R1 "Resistor" R0402 41.7,8.3 r270 top value=5K1
R2 "Resistor" R0402 42.85,8.3 r90 top value=1K8
R3 "Resistor" R0402 30.625,4.525 r90 top value=820R
R4 "Resistor" R0402 30.625,2.75 r90 top value=510R
R5 "" R0603 67,42.5 r0 top value=10K
R6 "Resistor" R0402 59.8,10.9 r0 top value=5K1
R7 "Resistor" R0402 68.1,11.175 r270 top value=5K1
R8 "Resistor" R0402 55.25,11.25 r90 bottom value=4K7
R9 "Resistor" R0402 54.2,11.25 r90 bottom value=4K7
R10 "Resistor" R0402 31.625,63.25 r270 bottom value=10K
R11 "Resistor" R0402 27.15,34.88 r90 bottom value=5K1
R12 "Resistor" R0402 37.475,44.6 r90 bottom value=100R
R13 "Resistor" R0402 28.5,34.43 r180 bottom value=100K
R14 "Resistor" R0402 28.5,36.75 r180 bottom value=100K
R15 "Resistor" R0402 27.15,37.2 r90 bottom value=5K1
R16 "Resistor" R0402 30.5,44.75 r90 bottom value=33R
R17 "Resistor" R0402 44.35,36.425 r0 bottom value=0R
R18 "Resistor" R0402 43.05,39.1 r0 bottom value=33R
R19 "Resistor" R0402 33.575,31.35 r270 bottom value=33R
R20 "Resistor" R0402 43.05,40.275 r0 bottom value=0R
R21 "Resistor" R0402 43.95,37.475 r0 bottom value=33R
R22 "Resistor" R0402 29.325,33.375 r180 bottom value=5K1
R23 "Resistor" R0402 29.325,32.325 r180 bottom value=10K
R24 "Resistor" R0402 29.325,29.125 r180 bottom value=0R
R25 "Resistor" R0402 35.525,44.6 r90 bottom value=3K
R26 "Resistor" R0402 29.325,31.25 r180 bottom value=10K
R27 "Resistor" R0402 29.325,30.175 r180 bottom value=10K
R28 "Resistor" R0402 43.125,35.325 r0 bottom value=10K
R29 "Resistor" R0402 19.525,26.195 r0 bottom value=3K
R30 "Resistor" R0402 21.775,26.195 r180 bottom value=3K9
R31 "Resistor" R0402 15.9,26.92 r180 bottom value=1K8
R32 "Resistor" R0402 15.9,25.845 r180 bottom value=1K3
R33 "Resistor" R0402 15.9,27.995 r180 bottom value=3K9
R34 "Resistor" R0402 16.4,32.6 r270 bottom value=100K
R35 "Resistor" R0402 49.75,15.5 r180 top value=1K
R36 "Resistor" R0402 49.75,17 r180 top value=330R
R37 "Resistor" R0402 49.75,11.75 r180 top value=1K
R38 "Resistor" R0402 49.75,13.25 r0 top value=330R
R39 "Resistor" R0402 21.775,27.2 r180 bottom value=100K
R40 "Resistor" R0402 20.87,32.25 r0 bottom value=100K
R41 "Resistor" R0402 67.625,26.25 r0 top value=510R
R42 "" R0402 62.375,27.75 r0 top value=0R
R43 "Resistor" R0402 9.3,28.1 r180 top value=1K
R44 "" R0402 57.525,23.602 r0 top value=0R
R45 "Resistor" R0402 26.375,63.6 r0 bottom value=5K6
R46 "" R0603 38.45,18.125 r0 bottom value=620K
R47 "Resistor" R0402 2.968,5.46 r0 bottom value=100R
R48 "" R0402 4.875,39.5 r0 top value=620R
R49 "Resistor" R0603 45.75,61 r180 top value=20R
R50 "Resistor" R0603 45.75,59.625 r180 top value=20R
R51 "Resistor" R0402 27.875,63.25 r90 bottom value=5K6
R52 "Resistor" R0402 27.875,61.5 r90 bottom value=5K6
R53 "Resistor" R0402 26.375,61.15 r0 bottom value=5K6
R54 "Resistor" R0402 41.625,57.5 r90 top value=2K2
R55 "Resistor" R0402 31.625,61.5 r270 bottom value=10K
R56 "Resistor" R0402 29.2,3.275 r0 top value=2K
R57 "Resistor" R0402 39.75,44.5 r90 bottom value=33R
R58 "Resistor" R0402 29.5,43.75 r90 top value=0R
R59 "Resistor" R0402 37.625,47.525 r180 top value=100K
R60 "Resistor" R0402 39.538,51.665 r0 top value=10K
R61 "Resistor" R0402 67.625,23.5 r0 top value=680R
R62 "Resistor" R0402 67.625,20.75 r0 top value=680R
R63 "Resistor" R0402 30.1,50.353 r0 top value=10K
R64 "Resistor" R0402 39.075,34.65 r180 top value=10K
SB1 "" SOLDER-BRIDGE_R0603-0R 21,10.75 r0 bottom
SB2 "" SOLDER-BRIDGE_R0603-0R 53.625,48 r180 bottom
SB3 "" SOLDER-BRIDGE_R0603-0R 52.75,64.5 r180 bottom
SB4 "" SOLDER-BRIDGE_R0603-0R 52.75,66 r180 bottom
SB5 "" SOLDER-BRIDGE_R0603-0R 5.5,48.75 r180 bottom
SB6 "" SOLDER-BRIDGE_R0603-0R 15.875,62.775 r180 bottom
SB7 "" SOLDER-BRIDGE_R0603-0R 44.475,56.075 r90 bottom
SB8 "" SOLDER-BRIDGE_R0603-0R 34.7,62.45 r90 bottom
SB9 "" SOLDER-BRIDGE_R0603-0R 33.075,64.3 r90 bottom
SB10 "" SOLDER-BRIDGE_R0603-0R 5.5,50.125 r180 bottom
SB11 "" SOLDER-BRIDGE_R0603-0R 52.75,67.5 r180 bottom
SB12 "" SOLDER-BRIDGE_R0603-0R 52.75,63 r180 bottom
SB13 "" SOLDER-BRIDGE_R0603-0R 4.85,43.825 r180 bottom
SB14 "" SOLDER-BRIDGE_R0603-0R 4.85,42.325 r180 bottom
SB15 "" SOLDER-BRIDGE_R0603-0R 4.85,40.825 r180 bottom
SB16 "" SOLDER-BRIDGE_R0603-0R 36.125,66.375 r90 bottom
SB17 "" SOLDER-BRIDGE_R0603-0R 37.5,66.375 r90 bottom
SB18 "" SOLDER-BRIDGE_R0603-0R 38.875,66.8 r270 bottom
SB19 "" SOLDER-BRIDGE_R0603-0R 45.875,66.5 r90 bottom
SB20 "" SOLDER-BRIDGE_R0603-0R 5.5,53 r180 bottom
SB21 "" SOLDER-BRIDGE_R0603-0R 5.5,51.625 r180 bottom
SB22 "" SOLDER-BRIDGE_R0603-0R 53.625,50.575 r0 bottom
SB23 "" SOLDER-BRIDGE_R0603-0R 5.5,54.5 r180 bottom
SB24 "" SOLDER-BRIDGE_R0603-0R 53.625,55.625 r0 bottom
SB25 "" SOLDER-BRIDGE_R0603-0R 5.5,55.875 r180 bottom
SB26 "" SOLDER-BRIDGE_R0603-0R 53.625,58.25 r0 bottom
SB27 "" SOLDER-BRIDGE_R0603-0R 15.875,65.35 r0 bottom
SB28 "" SOLDER-BRIDGE_R0603-0R 5.5,60.25 r180 bottom
SB29 "" SOLDER-BRIDGE_R0603-0R 15.875,66.75 r0 bottom
SB30 "" SOLDER-BRIDGE_R0603-0R 5.5,61.625 r180 bottom
SB31 "" SOLDER-BRIDGE_R0603-0R 53.625,44.225 r0 bottom
SB32 "" SOLDER-BRIDGE_R0603-0R 34.7,66.8 r90 bottom
SB33 "" SOLDER-BRIDGE_R0603-0R 65.25,35.25 r180 bottom
SB34 "" SOLDER-BRIDGE_R0603-0R 65.25,33.625 r180 bottom
SB35 "" SOLDER-BRIDGE_R0603-0R 53.625,41.425 r0 bottom
SB36 "" SOLDER-BRIDGE_R0603-0R 42.65,48.725 r0 bottom
SB37 "" SOLDER-BRIDGE_R0603-0R 42.65,47.225 r0 bottom
SB38 "" SOLDER-BRIDGE_R0603-0R 42.65,45.725 r0 bottom
SB39 "" SOLDER-BRIDGE_R0603-0R 10.925,67.325 r0 bottom
SB40 "" SOLDER-BRIDGE_R0603-0R 53.625,46.35 r0 bottom
SB41 "" SOLDER-BRIDGE_R0603-0R 53.625,42.825 r180 bottom
SB42 "" SOLDER-BRIDGE_R0603-0R 53.625,40.025 r180 bottom
STICKER-BOARD-1 "STICKER_BOARD" STICKER_BOARD_25X5 39.125,13.25 r0 bottom value="Sticker board"
STICKER-PRODUCT-1 "Comment" STICKER_PRODUCT_25X5 39.125,7.5 r180 bottom value=MB1801
TP1 "Test Point" TP_SMD_1MM 37.475,46.575 r90 bottom
TP2 "Test Point" TP_SMD_0-3MM 43.625,49.975 r90 bottom
U1 "ESDA6V1BC6" ESD_SOT23-6L 12.25,60.75 r270 top
U2 "ESD-TRANSIL" ESD_QFN1610_2N_1K_2A 65.875,11.625 r0 top value=ESDA25P35-1U1M
U3 "" ESD_ST0201 23.75,12.5 r0 bottom value=ESDALC6V1-1U2
U4 "ECMF2-40A100N6" ESD_UQFN-6L_1P45X1P4_P040 63.15,12.275 r0 top
U5 "ESDA6V1BC6" ESD_SOT23-6L 56.75,62.25 r270 top
U6 "STLINK-V3EC" ICC_UFBGA201_176+25_10X10_P065 36.175,37.8 r90 bottom value=STM32F723IEK6
U7 "ESD-TRANSIL" ESD_QFN1610_2N_1K_2A 11.625,17.125 r270 top value=ESDA25P35-1U1M
U8 "ECMF2-40A100N6" ESD_UQFN-6L_1P45X1P4_P040 12.28,19.85 r270 top
U9 "TPS259535DSG" ICC_WSON8-EPAD_2X2_P050 16.75,29.85 r270 bottom
U10 "STMPS2151STR" MOS_SOT23-5L 23.725,31.15 r180 bottom
U11 "ST730M33R" ICC_SOT23-5L_H1P45 42.625,28.595 r0 bottom
U12 "M95P32" ICC_SO8_5X4_P127 34.8,51.015 r90 top value=MP95P32
U13 "OLED_RITDISPLAY_9OL9935718000" OLED_RITDISPLAY_9OL9935718000 27.5,13.625 r0 top value=9OL9935718000
U14 "ESDALC6V1W5" ESD_SOT323-5L 10.75,6.25 r180 top
U15 "ESDALC6V1W5" ESD_SOT323-5L 10.75,11.375 r180 top
U16 "LP2985IM5-3.6/NOPB" REG_SOT23-5L 26,52.5 r270 bottom
U17 "ESD-TRANSIL" ESD_QFN1610_2N_1K_2A 7.375,38.5 r90 top value=ESDA7P120-1U1M
U18 "LD1117S33TR" REG_SOT223-TAB 34,51.25 r90 bottom
U19 "LD3985M18R" REG_SOT23-5L 41.25,52.25 r90 bottom
U20 "LD1117S50TR" REG_SOT223-TAB 19.25,51.5 r180 bottom
U21 "MP23DB01MMTR" MIC_STM_MP23DB01MMTR 56.5,67.25 r0 bottom value=MP23DB01HPTR
U22 "WM8904CGEFL/RV" ICC_QFN32-EPAD_4X4_P040 39.125,62 r0 bottom
X1 "XTAL_4_PINS" CRY_NX2016SA_4P 36.775,29.975 r180 bottom value=24MHz

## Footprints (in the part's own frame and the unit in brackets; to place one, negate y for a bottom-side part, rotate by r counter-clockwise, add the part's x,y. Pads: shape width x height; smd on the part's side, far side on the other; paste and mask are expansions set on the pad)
C0402 [mm]
  rect 0.51x0.56 smd mask+0.05: 1(-0.45,0) 2(0.45,0)
  body extent -0.5,-0.3 0.5,0.3, height 0.4
C0603 [mm]
  rect 0.64x0.89 smd mask+0.05: 1(-0.7,0) 2(0.7,0)
  silkscreen extent -0.9,-0.55 1.05,0.55, body extent -0.9,-0.5 0.9,0.5, height 1.4
C0805 [mm]
  rect 0.9x1.4 smd mask+0.05: 1(-0.85,0) 2(0.85,0)
  silkscreen extent -1.3,-0.77 1.3,0.77, body extent -1.1,-0.7 1.1,0.7, height 1.35
C0805_H0P85 [mm] "MCD-01525"
  rect 0.9x1.4 smd mask+0.05: 1(-0.85,0) 2(0.85,0)
  silkscreen extent -1.3,-0.77 1.3,0.77, body extent -1.1,-0.73 1.1,0.72, height 0.95
C6032-28_VISHAY_293D-CASE-C [mm] "MCD-03891"
  rect 2.2x2.8 smd mask+0.05: 1(-2.4,0) 2(2.4,0)
  silkscreen extent -3.64,-2.2 3.15,2.2, body extent -3.15,-1.75 3.15,1.75, height 2.8
CON_988-JIUBABA_A2006LF-04A [mm] "MCD-01741"
  rect 1.7x3.1 smd mask+0.05: 0(-5.2,0) 0(5.2,0)
  rect 1.1x4.6 smd mask+0.05: 1(3,2.75) 2(1,2.75) 3(-1,2.75) 4(-3,2.75)
  silkscreen extent -6.12,-2.55 6.12,2.8, body extent -6.12,-2.55 6.12,4, height 8.35
CON_MOLEX_53047-0210 [mm]
  oval 1x1.3 hole 0.5 mask+0.05: 1(-0.625,0) 2(0.625,0)
  silkscreen extent -2.12,-1.15 2.13,2.05, body extent -2.12,-1.15 2.13,2.05, height 4.2
CON_PHONE-JACK-3P5_HY_PJ3028B [mm]
  rect 1.5x2.5 smd mask+0.05: 2(1.25,-3.45) 7(2.85,3.45)
  rect 2x2.5 smd mask+0.05: 3(4,-3.45) 4(5.8,3.45) 6(13.2,-3.45)
  rect 2.5x2 smd mask+0.05: 5(17.25,0.75)
  round 0.5 hole 2 unplated mask+0.1: MT1(5,0) MT2(12,0)
  Multi-Layer keep-out circle w0.01: c5,0 r1.25
  Multi-Layer keep-out circle w0.01: c12,0 r1.25
  silkscreen extent -0.9,-3.7 16,3, body extent -0.9,-3 16,3, height 5
CON_SAMTEC_CLP-125-02-F-D [mm] "MCD-02705"
  rect 1.8x0.75 smd: 1(-1.5,15.24) 2(1.5,15.24) 3(-1.5,13.97) 4(1.5,13.97) 5(-1.5,12.7) 6(1.5,12.7) 7(-1.5,11.43) 8(1.5,11.43) 9(-1.5,10.16) 10(1.5,10.16) 11(-1.5,8.89) 12(1.5,8.89) 13(-1.5,7.62) 14(1.5,7.62) 15(-1.5,6.35) 16(1.5,6.35) 17(-1.5,5.08) 18(1.5,5.08) 19(-1.5,3.81) 20(1.5,3.81) 21(-1.5,2.54) 22(1.5,2.54) 23(-1.5,1.27) 24(1.5,1.27) 25(-1.5,0) 26(1.5,0) 27(-1.5,-1.27) 28(1.5,-1.27) 29(-1.5,-2.54) 30(1.5,-2.54) 31(-1.5,-3.81) 32(1.5,-3.81) 33(-1.5,-5.08) 34(1.5,-5.08) 35(-1.5,-6.35) 36(1.5,-6.35) 37(-1.5,-7.62) 38(1.5,-7.62) 39(-1.5,-8.89) 40(1.5,-8.89) 41(-1.5,-10.16) 42(1.5,-10.16) 43(-1.5,-11.43) 44(1.5,-11.43) 45(-1.5,-12.7) 46(1.5,-12.7) 47(-1.5,-13.97) 48(1.5,-13.97) 49(-1.5,-15.24) 50(1.5,-15.24)
  silkscreen extent -1.48,-16.09 1.49,16.09, body extent -2.16,-16.09 2.16,16.09, height 2.27
CON_SAMTEC_SSM-106-L-SV [mm] "MCD-02346"
  rect 1.02x1.905 smd mask+0.05: 1(-6.35,-1.602) 2(-3.81,1.603) 3(-1.27,-1.602) 4(1.27,1.603) 5(3.81,-1.602) 6(6.35,1.603)
  silkscreen extent -7.62,-1.27 7.62,1.27, body extent -7.62,-2.29 7.62,2.29, height 7.37
CON_SAMTEC_SSM-108-L-SV [mm] "MCD-02345"
  rect 1.02x1.905 smd mask+0.05: 1(-8.89,-1.602) 2(-6.35,1.603) 3(-3.81,-1.602) 4(-1.27,1.603) 5(1.27,-1.602) 6(3.81,1.603) 7(6.35,-1.602) 8(8.89,1.603)
  silkscreen extent -10.16,-1.27 10.16,1.27, body extent -10.16,-2.29 10.16,2.29, height 7.37
CON_SAMTEC_SSM-110-L-SV [mm] "MCD-02342"
  rect 1.02x1.905 smd mask+0.05: 1(-11.43,-1.602) 2(-8.89,1.603) 3(-6.35,-1.602) 4(-3.81,1.603) 5(-1.27,-1.602) 6(1.27,1.603) 7(3.81,-1.602) 8(6.35,1.603) 9(8.89,-1.602) 10(11.43,1.603)
  silkscreen extent -12.7,-1.27 12.7,1.27, body extent -12.7,-2.29 12.7,2.29, height 7.49
CON_SAMTEC_TSW-102-07-G-S [mm]
  rect 1.85x1.85 / inner round 1.85 / far side rect 1.85x1.85 hole 1 mask+0.05: 1(-1.27,0)
  round 1.85 hole 1 mask+0.05: 2(1.27,0)
  silkscreen extent -2.58,-1.3 2.58,1.3, body extent -2.67,-1.3 2.58,1.3, height 8.38
CON_SAMTEC_TSW-104-07-G-S [mm]
  rect 1.85x1.85 / inner round 1.85 / far side rect 1.85x1.85 hole 1 mask+0.05: 1(-3.81,0)
  round 1.85 hole 1 mask+0.05: 2(-1.27,0) 3(1.27,0) 4(3.81,0)
  silkscreen extent -5.12,-1.3 5.12,1.3, body extent -5.21,-1.37 5.18,1.37, height 8.38
CON_SAMTEC_TSW-105-07-X-D [mm]
  rect 1.85x1.85 / inner round 1.85 / far side rect 1.85x1.85 hole 1 mask+0.05: 1(-5.08,-1.27)
  round 1.85 hole 1 mask+0.05: 2(-5.08,1.27) 3(-2.54,-1.27) 4(-2.54,1.27) 5(0,-1.27) 6(0,1.27) 7(2.54,-1.27) 8(2.54,1.27) 9(5.08,-1.27) 10(5.08,1.27)
  silkscreen extent -6.35,-2.54 6.35,2.54, body extent -6.35,-2.54 6.35,2.55, height 8.38
CON_STDC14_Receiver_MEDIUM_WITH_MIPI10_3D [mm] "compatible with FTSH-105-01-L-DV,-K and FTSH-107-01-L-DV,-K,-A,-P,-ES"
  round 0 hole 1.19 unplated mask+0.05: 0(-5.445,0) 0(5.445,0)
  round 0 hole 0.97 unplated mask+0.05: 0(-3.175,0) 0(3.175,0)
  rect 0.74x2.79 smd mask+0.05: 1(-3.81,-2.032) 2(-3.81,2.032) 3(-2.54,-2.032) 4(-2.54,2.032) 5(-1.27,-2.032) 6(-1.27,2.032) 7(0,-2.032) 8(0,2.032) 9(1.27,-2.032) 10(1.27,2.032) 11(2.54,-2.032) 12(2.54,2.032) 13(3.81,-2.032) 14(3.81,2.032)
  silkscreen extent -6.3,-4.38 6.3,3.6, body extent -6.3,-2.92 6.3,2.92, height 6.6
CON_TAG-C_TC2050-IDC-NL [mm]
  round 0.9 smd paste+0 mask+0.05: 1(-2.54,-0.635) 2(-1.27,-0.635) 3(0,-0.635) 4(1.27,-0.635) 5(2.54,-0.635) 6(2.54,0.635) 7(1.27,0.635) 8(0,0.635) 9(-1.27,0.635) 10(-2.54,0.635)
  round 0 hole 1.1 unplated mask+0.05: 11(-3.81,0) 12(3.81,-1.015) 13(3.81,1.015)
  silkscreen extent -6.22,-3.4 6.22,3.33, body extent -6.28,-3.46 6.28,3.39, height 13
CON_USB-TYPEC_AMPHENOL_12401826E412A [mm] "MCD-03232"
  round 0 hole 0.65 unplated mask+0.05: 0(-3.6,0)
  round 0 hole 0.65 slot 0.95 at 0 deg unplated mask+0.05: 0(3.6,0)
  rect 0.3x0.7 smd mask+0.05: A1(-2.75,0.66) A2(-2.25,0.66) A3(-1.75,0.66) A4(-1.25,0.66) A5(-0.75,0.66) A6(-0.25,0.66) A7(0.25,0.66) A8(0.75,0.66) A9(1.25,0.66) A10(1.75,0.66) A11(2.25,0.66) A12(2.75,0.66) B1(2.5,-1.04) B2(2,-1.04) B3(1.5,-1.04) B4(1,-1.04) B5(0.5,-1.04) B6(0,-1.04) B7(-0.5,-1.04) B8(-1,-1.04) B9(-1.5,-1.04) B10(-2,-1.04) B11(-2.5,-1.04) B12(-3,-1.04)
  oval 0.8x1.4 hole 0.5 slot 1.1 at 90 deg mask+0.05: SH1(-4.13,-1.25) SH2(4.13,-1.25) SH3(-4.49,-4.7) SH4(4.49,-4.7)
  Top Layer keep-out region: -3.75,-7.24 3.75,-7.24 3.75,-1.95 -3.75,-1.95
  silkscreen extent -4.7,-9.59 4.7,0.91, body extent -4.6,-9.59 4.6,0.91, height 3.26
CPOL_TAJ-A_1206_H180 [mm]
  rect 1.45x1.6 smd mask+0.05: 1(-1.175,0) 2(1.175,0)
  silkscreen extent -2.15,-1.05 1.7,1.05, body extent -1.7,-0.9 1.7,0.9, height 1.8
CRY_NX2016SA_4P [mm]
  rect 0.85x0.75 smd mask+0.05: 1(-0.675,-0.525) 2(0.675,-0.525) 3(0.675,0.525) 4(-0.675,0.525)
  silkscreen extent -1.22,-1.02 1.05,0.85, body extent -1.05,-0.85 1.05,0.85, height 0.7
DIO_SOD323_1A_2K [mm]
  rect 1.06x0.54 smd mask+0.05: 1(-1.07,0) 2(1.07,0)
  silkscreen extent -0.9,-0.72 0.9,0.72, body extent -1.3,-0.78 1.3,0.78, height 1.17
ESD_QFN1610_2N_1K_2A [mm] "DFN, 2-Leads, Body 1.60x1.00mm"
  rect 0.55x0.9 smd mask+0.05: 1(-0.625,0) 2(0.625,0)
  silkscreen extent -1.02,-0.58 0.85,0.58, body extent -0.85,-0.55 0.85,0.55, height 0.6
ESD_SOT23-6L [mm]
  rect 0.6x1.2 smd mask+0.05: 1(-0.95,-1.15) 2(0,-1.15) 3(0.95,-1.15) 4(0.95,1.15) 5(0,1.15) 6(-0.95,1.15)
  silkscreen extent -1.53,-0.87 1.53,0.87, body extent -1.52,-1.5 1.52,1.5, height 1.45
ESD_SOT323-5L [mm]
  rect 0.4x1.2 smd mask+0.05: 1(-0.65,-0.85) 2(0,-0.85) 3(0.65,-0.85) 4(0.65,0.85) 5(-0.65,0.85)
  silkscreen extent -1.22,-1.21 1.22,0.77, body extent -1.15,-1.05 1.15,1.05, height 1.1
ESD_ST0201 [mm]
  rect 0.425x0.33 smd mask+0.05: 1(-0.312,0) 2(0.312,0)
  silkscreen extent -0.55,-0.3 -0.5,0.3, body extent -0.34,-0.18 0.34,0.18, height 0.34
ESD_UQFN-6L_1P45X1P4_P040 [mm] "MCD-03060"
  rect 0.2x0.7 smd mask+0.05: 1(-0.4,-0.525) 2(0,-0.525) 3(0.4,-0.525) 4(0.4,0.525) 5(0,0.525) 6(-0.4,0.525)
  body extent -0.72,-0.7 0.72,0.7, height 0.51
ICC_QFN32-EPAD_4X4_P040 [mm] "MCD-03196"
  rect 0.22x0.3 smd mask+0.05: 1(-1.4,-2) 8(1.4,-1.925) 17(1.4,1.925) 24(-1.4,1.925)
  rect 0.22x0.66 smd mask+0.05: 2(-1,-1.925) 3(-0.6,-1.925) 4(-0.2,-1.925) 5(0.2,-1.925) 6(0.6,-1.925) 7(1,-1.925) 18(1,1.925) 19(0.6,1.925) 20(0.2,1.925) 21(-0.2,1.925) 22(-0.6,1.925) 23(-1,1.925)
  rect 0.3x0.22 smd mask+0.05: 9(1.925,-1.4) 16(1.925,1.4) 25(-1.925,1.4) 32(-1.925,-1.4)
  rect 0.66x0.22 smd mask+0.05: 10(1.925,-1) 11(1.925,-0.6) 12(1.925,-0.2) 13(1.925,0.2) 14(1.925,0.6) 15(1.925,1) 26(-1.925,1) 27(-1.925,0.6) 28(-1.925,0.2) 29(-1.925,-0.2) 30(-1.925,-0.6) 31(-1.925,-1)
  rect 2.8x2.8 smd mask+0.05: 33(0,0)
  Top Layer region: 1.29,-2.255 1.29,-1.595 1.35,-1.595 1.51,-1.755 1.51,-2.255
  Top Layer region: -1.29,-2.255 -1.29,-1.595 -1.35,-1.595 -1.51,-1.755 -1.51,-2.255
  Top Layer region: -2.255,-1.29 -1.595,-1.29 -1.595,-1.35 -1.755,-1.51 -2.255,-1.51
  Top Layer region: -2.255,1.29 -1.595,1.29 -1.595,1.35 -1.755,1.51 -2.255,1.51
  Top Layer region: 2.255,1.29 1.595,1.29 1.595,1.35 1.755,1.51 2.255,1.51
  Top Layer region: 2.255,-1.29 1.595,-1.29 1.595,-1.35 1.755,-1.51 2.255,-1.51
  Top Layer region: 1.29,2.255 1.29,1.595 1.35,1.595 1.51,1.755 1.51,2.255
  Top Layer region: -1.29,2.255 -1.29,1.595 -1.35,1.595 -1.51,1.755 -1.51,2.255
  silkscreen extent -2.25,-2.25 -1.68,-1.68, body extent -2.01,-2.01 2,2.01, height 0.91
ICC_SO8_5X4_P127 [mm]
  rect 0.7x1.75 smd mask+0.05: 1(-1.905,-2.375) 2(-0.635,-2.375) 3(0.635,-2.375) 4(1.905,-2.375) 5(1.905,2.375) 6(0.635,2.375) 7(-0.635,2.375) 8(-1.905,2.375)
  silkscreen extent -2.73,-3.25 2.58,2, body extent -2.57,-3 2.57,3, height 1.75
ICC_SOT23-5L_H1P45 [mm]
  rect 0.6x1.3 smd mask+0.05: 1(-0.95,-1.1) 2(0,-1.1) 3(0.95,-1.1) 4(0.95,1.1) 5(-0.95,1.1)
  silkscreen extent -1.75,-1.68 1.6,0.97, body extent -1.52,-1.25 1.52,1.25, height 1.45
ICC_UFBGA201_176+25_10X10_P065 [mm] "IPC"
  round 0.25 smd mask+0.038: A1(-4.55,4.55) A2(-3.9,4.55) A3(-3.25,4.55) A4(-2.6,4.55) A5(-1.95,4.55) A6(-1.3,4.55) A7(-0.65,4.55) A8(0,4.55) A9(0.65,4.55) A10(1.3,4.55) A11(1.95,4.55) A12(2.6,4.55) A13(3.25,4.55) A14(3.9,4.55) A15(4.55,4.55) B1(-4.55,3.9) B2(-3.9,3.9) B3(-3.25,3.9) B4(-2.6,3.9) B5(-1.95,3.9) B6(-1.3,3.9) B7(-0.65,3.9) B8(0,3.9) B9(0.65,3.9) B10(1.3,3.9) B11(1.95,3.9) B12(2.6,3.9) B13(3.25,3.9) B14(3.9,3.9) B15(4.55,3.9) C1(-4.55,3.25) C2(-3.9,3.25) C3(-3.25,3.25) C4(-2.6,3.25) C5(-1.95,3.25) C6(-1.3,3.25) C7(-0.65,3.25) C8(0,3.25) C9(0.65,3.25) C10(1.3,3.25) C11(1.95,3.25) C12(2.6,3.25) C13(3.25,3.25) C14(3.9,3.25) C15(4.55,3.25) D1(-4.55,2.6) D2(-3.9,2.6) D3(-3.25,2.6) D4(-2.6,2.6) D5(-1.95,2.6) D6(-1.3,2.6) D7(-0.65,2.6) D8(0,2.6) D9(0.65,2.6) D10(1.3,2.6) D11(1.95,2.6) D12(2.6,2.6) D13(3.25,2.6) D14(3.9,2.6) D15(4.55,2.6) E1(-4.55,1.95) E2(-3.9,1.95) E3(-3.25,1.95) E4(-2.6,1.95) E12(2.6,1.95) E13(3.25,1.95) E14(3.9,1.95) E15(4.55,1.95) F1(-4.55,1.3) F2(-3.9,1.3) F3(-3.25,1.3) F4(-2.6,1.3) F6(-1.3,1.3) F7(-0.65,1.3) F8(0,1.3) F9(0.65,1.3) F10(1.3,1.3) F12(2.6,1.3) F13(3.25,1.3) F14(3.9,1.3) F15(4.55,1.3) G1(-4.55,0.65) G2(-3.9,0.65) G3(-3.25,0.65) G4(-2.6,0.65) G6(-1.3,0.65) G7(-0.65,0.65) G8(0,0.65) G9(0.65,0.65) G10(1.3,0.65) G12(2.6,0.65) G13(3.25,0.65) G14(3.9,0.65) G15(4.55,0.65) H1(-4.55,0) H2(-3.9,0) H3(-3.25,0) H4(-2.6,0) H6(-1.3,0) H7(-0.65,0) H8(0,0) H9(0.65,0) H10(1.3,0) H12(2.6,0) H13(3.25,0) H14(3.9,0) H15(4.55,0) J1(-4.55,-0.65) J2(-3.9,-0.65) J3(-3.25,-0.65) J4(-2.6,-0.65) J6(-1.3,-0.65) J7(-0.65,-0.65) J8(0,-0.65) J9(0.65,-0.65) J10(1.3,-0.65) J12(2.6,-0.65) J13(3.25,-0.65) J14(3.9,-0.65) J15(4.55,-0.65) K1(-4.55,-1.3) K2(-3.9,-1.3) K3(-3.25,-1.3) K4(-2.6,-1.3) K6(-1.3,-1.3) K7(-0.65,-1.3) K8(0,-1.3) K9(0.65,-1.3) K10(1.3,-1.3) K12(2.6,-1.3) K13(3.25,-1.3) K14(3.9,-1.3) K15(4.55,-1.3) L1(-4.55,-1.95) L2(-3.9,-1.95) L3(-3.25,-1.95) L4(-2.6,-1.95) L12(2.6,-1.95) L13(3.25,-1.95) L14(3.9,-1.95) L15(4.55,-1.95) M1(-4.55,-2.6) M2(-3.9,-2.6) M3(-3.25,-2.6) M4(-2.6,-2.6) M5(-1.95,-2.6) M6(-1.3,-2.6) M7(-0.65,-2.6) M8(0,-2.6) M9(0.65,-2.6) M10(1.3,-2.6) M11(1.95,-2.6) M12(2.6,-2.6) M13(3.25,-2.6) M14(3.9,-2.6) M15(4.55,-2.6) N1(-4.55,-3.25) N2(-3.9,-3.25) N3(-3.25,-3.25) N4(-2.6,-3.25) N5(-1.95,-3.25) N6(-1.3,-3.25) N7(-0.65,-3.25) N8(0,-3.25) N9(0.65,-3.25) N10(1.3,-3.25) N11(1.95,-3.25) N12(2.6,-3.25) N13(3.25,-3.25) N14(3.9,-3.25) N15(4.55,-3.25) P1(-4.55,-3.9) P2(-3.9,-3.9) P3(-3.25,-3.9) P4(-2.6,-3.9) P5(-1.95,-3.9) P6(-1.3,-3.9) P7(-0.65,-3.9) P8(0,-3.9) P9(0.65,-3.9) P10(1.3,-3.9) P11(1.95,-3.9) P12(2.6,-3.9) P13(3.25,-3.9) P14(3.9,-3.9) P15(4.55,-3.9) R1(-4.55,-4.55) R2(-3.9,-4.55) R3(-3.25,-4.55) R4(-2.6,-4.55) R5(-1.95,-4.55) R6(-1.3,-4.55) R7(-0.65,-4.55) R8(0,-4.55) R9(0.65,-4.55) R10(1.3,-4.55) R11(1.95,-4.55) R12(2.6,-4.55) R13(3.25,-4.55) R14(3.9,-4.55) R15(4.55,-4.55)
  silkscreen extent -5.22,-5.07 5.07,5.23, body extent -5.07,-5.07 5.07,5.07, height 0.61
ICC_WSON8-EPAD_2X2_P050 [mm] "MCD-02194"
  rect 0.5x0.3 smd paste+0 mask+0.05: 1(-0.9,0.75) 2(-0.9,0.25) 3(-0.9,-0.25) 4(-0.9,-0.75) 5(0.9,-0.75) 6(0.9,-0.25) 7(0.9,0.25) 8(0.9,0.75)
  rect 0.9x1.6 smd paste+0 mask+0.05: 9(0,0)
  silkscreen extent -0.5,-1 0.5,1, body extent -1,-1 1,1, height 0.81
IND_0402_MURATA_BLM15H_H0P5 [mm] "MCD-01610"
  rect 0.65x0.9 smd mask+0.05: 1(-0.475,0) 2(0.475,0)
  body extent -0.53,-0.28 0.53,0.28, height 0.55
LED_0603_OSRAM_LG-Q396-PS-35_GREEN_1A2K_H0P4 [mm]
  rect 0.8x0.8 smd mask+0.05: 1(-0.75,0) 2(0.75,0)
  silkscreen extent -0.85,-0.53 1.28,0.53, body extent -0.85,-0.45 0.85,0.45, height 0.6
LED_0603_VISHAY_VLMB1300-GS08_BLUE_1A2K_H0P8 [mm]
  rect 0.8x0.8 smd mask+0.05: 1(-0.75,0) 2(0.75,0)
  silkscreen extent -0.85,-0.53 1.28,0.53, body extent -0.85,-0.45 0.85,0.45, height 0.8
LED_0603_VISHAY_VLMS1300-GS08_RED_1A2K_H0P8 [mm]
  rect 0.8x0.8 smd mask+0.05: 1(-0.75,0) 2(0.75,0)
  silkscreen extent -0.85,-0.53 1.28,0.53, body extent -0.85,-0.45 0.85,0.45, height 0.8
LED_0603_VISHAY_VLMTG1300-GS08_GREEN_1A2K_H0P8 [mm]
  rect 0.8x0.8 smd mask+0.05: 1(-0.75,0) 2(0.75,0)
  silkscreen extent -0.85,-0.53 1.28,0.53, body extent -0.85,-0.45 0.85,0.45, height 0.8
LED_BI-GR_WE-150141SV73110 [mm] "MCD-02631"
  rect 1.1x1.5 smd mask+0.05: 1(-0.75,1.5) 2(0.75,1.5) 3(-0.75,-1.5) 4(0.75,-1.5)
  silkscreen extent -1.65,-1.85 1.5,1.7, body extent -1.5,-1.85 1.5,1.85, height 2.1
LINK200 [mm]
  rect 0.2x0.35 smd paste-10 mask+0.05: 1(0,-0.225) 2(0,0.225)
MIC_STM_MP23DB01MMTR [mm]
  rect 0.725x0.522 smd mask+0.05: 1(-0.838,1.364) 2(-0.838,0.542) 4(0.838,0.542) 5(0.838,1.364)
  round 0.2 smd mask+0.05: 3(0,-1.373)
  round 0 hole 0.5 unplated mask+0.05: 6(0,-0.71)
  Top Layer circle w0.3: c0,-0.71 r0.663
  silkscreen extent -1.33,-1.75 1.33,1.75, body extent -1.33,-1.76 1.33,1.75, height 1.09
MIRE_PLACE_SMD_1MM [mm]
  round 1 smd paste-10 mask+1: 1(0,0)
  Top Layer keep-out circle w0.01: c0,0 r1.5
MOS_SOT23-5L [mm]
  rect 0.6x1.3 smd mask+0.05: 1(-0.95,-1.1) 2(0,-1.1) 3(0.95,-1.1) 4(0.95,1.1) 5(-0.95,1.1)
  silkscreen extent -1.6,-0.95 1.6,0.97, body extent -1.52,-1.25 1.52,1.25, height 1.45
NPN_SOT416-FL_EMT3F_1616_SC89 [mm]
  rect 0.46x0.65 smd mask+0.05: 1(-0.5,-0.525) 2(0.5,-0.525) 3(0,0.525)
  silkscreen extent -0.85,-0.48 0.85,0.48, body extent -0.85,-0.85 0.85,0.85, height 0.85
OLED_RITDISPLAY_9OL9935718000 [mm] "OLED, 20-Leads, Body 13.86x23.74mm, Pitch 0.70mm"
  rect 0.45x3 smd mask+0.051: 1(0.45,4.5) 2(1.15,4.5) 3(1.85,4.5) 4(2.55,4.5) 5(3.25,4.5) 6(3.95,4.5) 7(4.65,4.5) 8(5.35,4.5) 9(6.05,4.5) 10(6.75,4.5) 11(7.45,4.5) 12(8.15,4.5) 13(8.85,4.5) 14(9.55,4.5) 15(10.25,4.5) 16(10.95,4.5) 17(11.65,4.5) 18(12.35,4.5) 19(13.05,4.5) 20(13.75,4.5)
  round 0.5 hole 0.8 unplated: H1(0,0) H1(14.2,0)
  Top Layer keep-out region: -0.984,1.05 1.05,1.05 1.05,-0.903 2.016,-0.903 2.016,-1.75 12.216,-1.75 12.216,-0.903 13.2,-0.903 13.2,1.05 15.216,1.05 15.216,4.597 15.216,4.697 15.14,4.88 14.999,5.021 14.815,5.097 14.716,5.097 14.275,5.097 14.275,2.35 -0.075,2.35 -0.075,5.097 -0.483,5.097 -0.582,5.098 -0.767,5.022 -0.908,4.881 -0.984,4.697 -0.984,4.597
  Keep-Out Layer circle w0.4: c14.2,0 r0.7
  Keep-Out Layer circle w0.4: c0,0 r0.7
  silkscreen extent -5.39,-1.54 19.56,17.61, body extent -5.38,-1.55 19.58,17.6, height 4.2
R0402 [mm]
  rect 0.51x0.7 smd mask+0.05: 1(-0.45,0) 2(0.45,0)
  body extent -0.52,-0.3 0.52,0.3, height 0.4
R0603 [mm]
  rect 0.64x1 smd mask+0.05: 1(-0.7,0) 2(0.7,0)
  silkscreen extent -1.05,-0.58 1.05,0.58, body extent -0.9,-0.5 0.9,0.5, height 0.56
REG_SOT23-5L [mm]
  rect 0.6x1.3 smd mask+0.05: 1(-0.95,-1.1) 2(0,-1.1) 3(0.95,-1.1) 4(0.95,1.1) 5(-0.95,1.1)
  silkscreen extent -1.6,-0.95 1.6,0.97, body extent -1.52,-1.25 1.52,1.25, height 1.1
REG_SOT223-TAB [mm]
  rect 1.5x1.65 smd mask+0.05: 1(-2.3,-3.175) 2(0,-3.175) 3(2.3,-3.175)
  rect 3.5x1.65 smd mask+0.05: 4(0,3.175)
  silkscreen extent -3.35,-2.15 3.35,2.12, body extent -3.35,-3.48 3.35,3.48, height 1.8
Sheetbox_4L2S [mil] "Sheetbox 4 layers / 2 silkscreens"
  round 20 on Mech16: 1(813.78,210.69) 1(2736.9,210.69)
SOLDER-BRIDGE_R0603-0R [mil]
  round 10 smd paste-393.7: 1(-19.69,0) 2(23.62,0)
  Top Layer region: -47.24,-19.68 -47.24,19.68 -17.72,19.69 1.97,0 -17.72,-19.68
  Top Layer region: -3.94,19.69 15.75,0 -3.94,-19.68 47.24,-19.68 47.24,19.68
  silkscreen extent -50,-23 50,23, body extent -36,-20 36,20, height 22
STICKER_BOARD_25X5 [mm] "Sticker to mention board reference + serial number"
  silkscreen extent -12.5,-2.5 12.5,2.5
STICKER_PRODUCT_25X5 [mm] "Sticker to mention board CPN code"
  silkscreen extent -12.5,-2.5 12.5,2.5
SWI_C&K_KSC321GLFS_BLACK [mm] "BLACK"
  rect 3.1x1 smd mask+0.05: 1(-4.45,2) 2(4.45,2) 3(-4.45,-2) 4(4.45,-2)
  silkscreen extent -3.25,-3.25 3.25,3.25, body extent -5,-3.25 5,3.25, height 3.5
SWI_XIEJIA_MT-008A_6P [mm] "MCD-00132"
  rect 1.8x1.1 smd mask+0.05: 1(-3.1,1.4) 2(-3.1,0) 3(-3.1,-1.4) 4(3.1,1.4) 5(3.1,0) 6(3.1,-1.4)
  rect 2.2x1.4 smd mask+0.05: 7(0,3.75) 8(0,-3.75)
  round 0 hole 0.8 unplated paste-2539.97 mask+0.05: NPTH1(0,1.9)
  round 0 hole 1.1 unplated paste-2539.97 mask+0.05: NPTH2(0,-1.9)
  silkscreen extent -3.7,-3.7 3.7,3.7, body extent -3.85,-3.75 3.85,3.75, height 5.2
TP_SMD_0-3MM [mm]
  round 0.3 smd paste-10 mask+0.05: 1(0,0)
  silkscreen extent -0.3,-0.3 0.3,0.3
TP_SMD_1MM [mm]
  round 1 smd paste-10 mask+0.05: 1(0,0)
  silkscreen extent -0.7,-0.7 0.7,0.7

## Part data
B1: library part MCD-00132, "Joystick, 4 dir, 1 OK", Manufacturer="XIEJIA ELECTRONICS", Manufacturer_Part_Number=MT-008A
B3: library part MCD-00175, "Switch HW BLACK High3.5mm 2Newtons", Manufacturer=C&K, Manufacturer_Part_Number=KSC321GLFS
C1 C2 C3 C4 C5 C6: library part MCD-01550, "Capacitor, MLCC, 1uF, 16V, X5R, +/-10%, 0805, T=0.85mm", Manufacturer=YAGEO, Manufacturer_Part_Number=CC0805KRX5R7BB105, Package=0805
C7 C8 C9 C10 C11 C44 C46: library part MCD-02355, "Capacitor, MLCC, 100nF, 25V, X7R, +/-10%, 0402, T=0.5mm", Manufacturer=WALSIN, Manufacturer_Part_Number=0402B104K250CT, Package=0402
C12 C23 C88: library part MCD-00095, "Capacitor, MLCC, 1uF, 25V, X5R, +/-10%, 0402, T=0,5mm", Alternate_Manufacturer=MURATA, Alternate_Manufacturer_Part_Number=GRM155R60J105KE19, Manufacturer_Part_Number=GRM155R61E105KA12, Package=C0402
C13: library part MCD-00011, "Capacitor, MLCC, 10nF, 16V, X7R, +/-10%, 0402, T=0.5mm", Alternate_Manufacturer=N/A, Manufacturer=YAGEO, Manufacturer_Part_Number=CC0402KRX7R7BB103, Package=0402
C14 C35: library part MCD-00205, "Capacitor, MLCC, 100pF, 50V, NPO, +/-5%, 0402, T=0.5mm", Manufacturer=YAGEO, Manufacturer_Part_Number=CC0402JRNPO9BN101, Package=0402
C15: library part MCD-00006, "Capacitor, MLCC, 100nF, 16V, X7R, 10%, 0402, T=0.5mm", Manufacturer=YAGEO, Manufacturer_Part_Number=CC0402KRX7R7BB104, Package=C0402
C16 C25: library part MCD-03891, "Capacitor, Tantalum, 10uF, 16V, 1.8R, +/-10%, 6032, T=2.5mm", Manufacturer=VISHAY, Manufacturer_Part_Number=293D106X9016C2TE3, Package=6032
C17 C21 C22: library part MCD-00012, "Capacitor, MLCC, 2.2uF, 10V, X5R, +/- 10%, 0603, T=0.8mm", Manufacturer=YAGEO, Manufacturer_Part_Number=CC0603KRX5R6BB225, Package=0603
C18 C24: library part MCD-01225, "Capacitor, MLCC, 220pF, 50V, NPO, +/-5%, 0402, T=0.5mm", Manufacturer=YAGEO, Manufacturer_Part_Number=CC0402JRNPO9BN221, Package=0402
C19 C27 C31 C32 C89 C91 C93: library part MCD-00009, "Capacitor, MLCC, 4.7uF, 16V, X5R, +/-10%, 0603, T=0.8mm", Manufacturer=YAGEO, Manufacturer_Part_Number=CC0603KRX5R7BB475, Package=0603
C20 C26 C28 C33 C41 C50 C51 C52 C53 C54 C55 C56 C57 C58 C61 C62 C63 C64 C65 C66 C67 C68 C70 C87 C90 C92 C94: library part MCD-00006, "Capacitor, MLCC, 100nF, 16V, X7R, +/-10%, 0402, T=0.5mm", Manufacturer=YAGEO, Manufacturer_Part_Number=CC0402KRX7R7BB104, Package=0402
C29 C30: library part MCD-00724, "Capacitor, MLCC, 470pF, 50V, NPO, +/-5%, 0402, T=0.5mm", Manufacturer=YAGEO, Manufacturer_Part_Number=CC0402JRNPO9BN471, Package=0402
C34 C85 C86: library part MCD-01722, "Capacitor, 1uF, 10V, X5R, 10%, 0402, T=0.5mm", Manufacturer=YAGEO, Manufacturer_Part_Number=CC0402KRX5R6BB105, Package=C0402
C36: library part MCD-00016, "Capacitor, MLCC, 20pF, 50V, NPO, +/- 5%, 0402, T=0.5mm", Manufacturer=YAGEO, Manufacturer_Part_Number=CC0402JRNPO9BN200, Package=0402
C37 C38 C45 C95: library part MCD-02198, "Capacitor, MLCC, 10nF, 50V, X7R, +/-10%, 0402, T=0.5mm", Manufacturer=YAGEO, Manufacturer_Part_Number=CC0402KRX7R9BB103, Package=0402
C39 C40: library part MCD-01374, "Capacitor, MLCC, 5.6pF, 50V, NPO, +/-0.1pF, 0402, T=0.5mm", Manufacturer=YAGEO, Manufacturer_Part_Number=CC0402BRNPO9BN5R6, Package=0402
C42 C48 C49: library part MCD-02606, "Capacitor, MLCC, 2.2uF, 6.3V, X5R, +/-10%, 0402, T=0.5mm", Manufacturer=YAGEO, Manufacturer_Part_Number=CC0402KRX5R5BB225, Package=0402
C43 C47 C60: library part MCD-00099, "Capacitor, MLCC, 10uF, 10V, X5R, +/-10%, 0603, T=0.8mm", Manufacturer=MURATA, Manufacturer_Part_Number=GRM188R61A106KE69D, Package=0603
C59: library part MCD-02372, "Capacitor, MLCC, 2.2uF, 25V, X7R, +/-10%, 0805, T=1,25mm", Manufacturer=MURATA, Manufacturer_Part_Number=GRM21BR71E225KE11L, Package=0805
C69: library part MCD-00006, "Capacitor,100nF,16V,X7R,10%,0402", Manufacturer=YAGEO, Manufacturer_Part_Number=CC0402KRX7R7BB104, Package=C0402
C71 C72 C74 C75 C78: library part MCD-00010, "Capacitor, MLCC, 1uF, 16V, X5R, 10%, 0603, T=0,8mm", Manufacturer=YAGEO, Manufacturer_Part_Number=CC0603KRX5R7BB105, Package=C0603
C73 C76: library part MCD-01043, "Capacitor, Tantalum, 4.7µF, 25V, 10%, 1206", Manufacturer=VISHAY, Manufacturer_Part_Number=293D475X9025A2TE3, Package=CPOL_TAJ-A_1206_H180
C77: library part MCD-00654, "Capacitor,2.2uF,16V, X5R,10%,0603,YAGEO", Manufacturer=YAGEO, Manufacturer_Part_Number=CC0603KRX5R7BB225, Package=C0603
C79 C82: library part MCD-00011, "Capacitor, MLCC, 10nF, 16V, X7R, 10%, 0402, T=0.5mm", Manufacturer=YAGEO, Manufacturer_Part_Number=CC0402KRX7R7BB103, Package=C0402
C80 C81 C83 C84: library part MCD-00099, "Capacitor, MLCC, 10uF, 10V, X5R, 10%, 0603, T=0,8mm", Manufacturer=MURATA, Manufacturer_Part_Number=GRM188R61A106KE69D, Package=C0603
CN1 CN2: library part MCD-02705, "Socket, 25x2, 1.27mm, VR, SMD, T=2.29mm", Manufacturer=SAMTEC
CN3 CN4: library part MCD-00263, "Connector Jack Socket Stereo 3.5mm, 4 pins, RA, SMT, Black", Manufacturer=QIAOD, Manufacturer_Part_Number=PJ3028B-3_4P
CN5 CN6: library part MCD-03232, "USB_TypeC, 24 pins, RA, SMD, T=2.96mm", Manufacturer="AMPHENOL ICC", Manufacturer_Part_Number=12401826E412A
CN7: library part MCD-00029, "Header, 4x1, 2.54mm, VR, TH, T=5.84mm/2.54mm", Manufacturer=SAMTEC, Manufacturer_Part_Number=TSW-104-07-G-S
CN8: library part MCD-02342, "Socket, 10x1, 2.54mm, VR, SMT, Height 7.37mm", Manufacturer=SAMTEC, Manufacturer_Part_Number=SSM-110-L-SV, Package="Surface Mount"
CN9 CN10: library part MCD-02345, "Socket, 8x1, 2.54mm, VR, SMT, Height 7.37mm", Manufacturer=SAMTEC, Manufacturer_Part_Number=SSM-108-L-SV, Package="Surface Mount"
CN11: library part MCD-02346, "Socket, 6x1, 2.54mm, VR, SMT, Height 7.37mm", Manufacturer=SAMTEC, Manufacturer_Part_Number=SSM-106-L-SV, Package="Surface Mount"
CN12: library part MCD-03083, "GROVE female header, SMD, 4 POS, 2.0mm", Manufacturer="SEEED TECHNOLOGY", Manufacturer_Part_Number=114020161, Package=NA
CN14: library part MCD-01226, "Header 5x2, 1.27mm, Dual row, Straight, Surface mount, vertical male connector. 3.05mm lead. Mates with FFSD connector. Footprint compatible with FTSH-107-01-L-DV,-K,-A,-P,-ES (STDC14 MEDIUM)", Manufacturer=SAMTEC, Manufacturer_Part_Number=FTSH-105-01-L-DV-K
CN15: library part MCD-00031, "Header_Plug-of-nails, 5x2, 1.27mm, No legs", Manufacturer=N/A
CN16: library part MCD-00655, "Header, 2x1, 1.25mm, VR, TH, T=2.25mm/2.3mm", Manufacturer=MOLEX, Manufacturer_Part_Number=53047-0210
D1 D2: library part MCD-03011, "Signal Schottky Diode, If=1A, Ifsm=5A, Vf =0.54V@1A, Vrrm=23V, Ir = 0.65µA@5V, SOD-323", Manufacturer=STMICROELECTRONICS, Manufacturer_Part_Number=BAT20JFILM, Package=SOD-323
JP1: library part MCD-00045, "Header, 2x1, 2.54mm, VR, TH, T=5.84mm/2.54mm", Manufacturer=SAMTEC, Manufacturer_Part_Number=TSW-102-07-G-S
